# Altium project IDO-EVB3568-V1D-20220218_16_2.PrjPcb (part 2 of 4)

## Sheet P07.SchDoc
size 420 x 297 mm
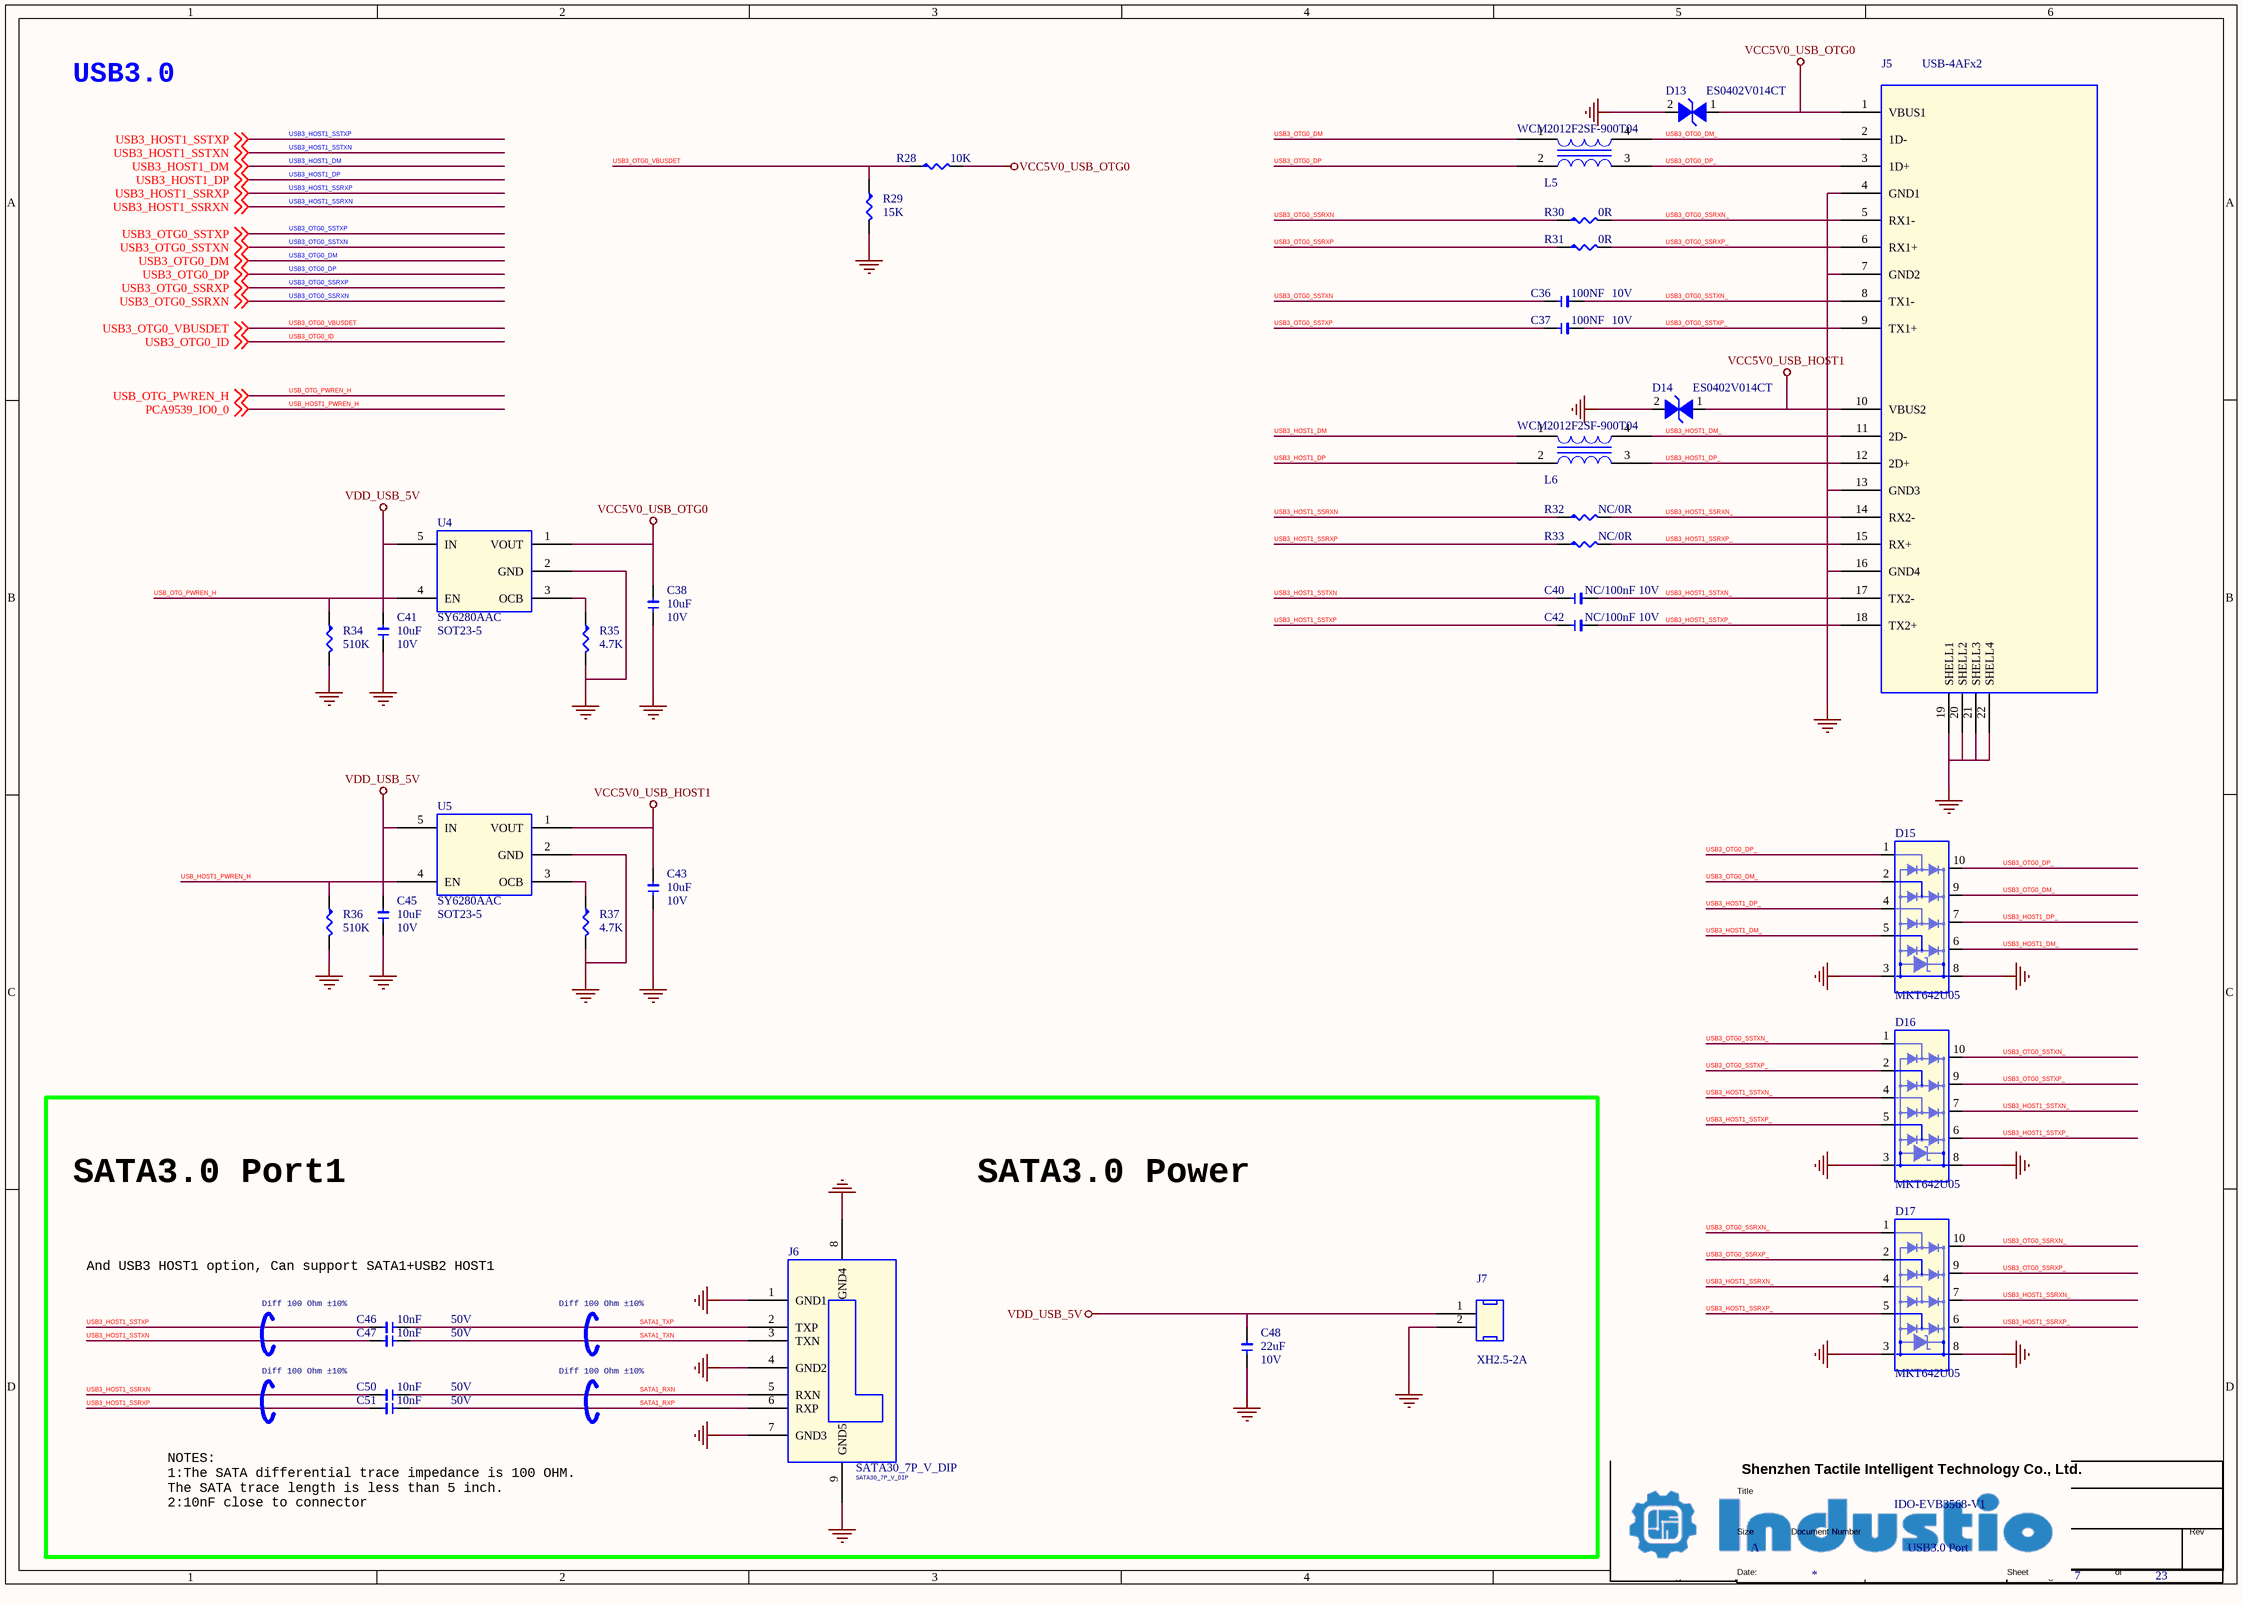
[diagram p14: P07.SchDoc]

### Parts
(Parts that share a designator on the sheet are numbered #1, #2 ... from top to bottom, then left to right.)
*#7  Doc: USB3.0 Port  Title: IDO-EVB3568-V1  Page Size: A  Page Number: 7  Page Count: 23  (hidden comment: TitleBlock1)  (graphical)
C36  100NF  DSC2: 10V  [1206]
C37  100NF  DSC2: 10V  [1206]
C38  10uF  DSC2: 10V  [1206]
C40  NC/100nF  DSC2: 10V  [1206]
C41  10uF  DSC2: 10V  [1206]
C42  NC/100nF  DSC2: 10V  [1206]
C43  10uF  DSC2: 10V  [1206]
C45  10uF  DSC2: 10V  [1206]
C46  10nF  DSC2: 50V  [1206]
C47  10nF  DSC2: 50V  [1206]
C48  22uF  DSC2: 10V  [1206]
C50  10nF  DSC2: 50V  [1206]
C51  10nF  DSC2: 50V  [1206]
D13  ES0402V014CT  [V0402]
D14  ES0402V014CT  [V0402]
D15  MKT642U05  [ESD-DFN2510A-10]
D16  MKT642U05  [ESD-DFN2510A-10]
D17  MKT642U05  [ESD-DFN2510A-10]
J5  USB-4AFx2  [USB3D0_AF_18P]
J6  SATA30_7P_V_DIP  [SATA30_7P_V_DIP]
J7  XH2.5-2A  [XH250-2A]
L5  WCM2012F2SF-900T04  [CMLS-ACM2012]
L6  WCM2012F2SF-900T04  [CMLS-ACM2012]
R28  10K  [R0402L]
R29  15K  [R0402L]
R30  0R  [R0402L]
R31  0R  [R0402L]
R32  NC/0R  [R0402L]
R33  NC/0R  [R0402L]
R34  510K  [R0402L]
R35  4.7K  [R0402L]
R36  510K  [R0402L]
R37  4.7K  [R0402L]
U4  SY6280AAC  [SOT23-5]
U5  SY6280AAC  [SOT23-5]

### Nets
GND: C38.1 C41.1 C43.1 C45.1 C48.1 D13.2(I/O1) D14.2(I/O1) D15.3 D15.8 D16.3 D16.8 D17.3 D17.8 J5.4(GND1) J5.7(GND2) J5.13(GND3) J5.16(GND4) J5.19(SHELL1) J5.20(SHELL2) J5.21(SHELL3) J5.22(SHELL4) J6.1(GND1) J6.4(GND2) J6.7(GND3) J6.8(GND4) J6.9(GND5) J7.2 R29.2 R34.2 R35.2 R36.2 R37.2 U4.2(GND) U5.2(GND)
VCC5V0_USB_HOST1: C43.2 D14.1(I/O2) J5.10(VBUS2) U5.1(VOUT)
VCC5V0_USB_OTG0: C38.2 D13.1(I/O2) J5.1(VBUS1) R28.2 U4.1(VOUT)
VDD_USB_5V: C41.2 C45.2 C48.2 J7.1 U4.5(IN) U5.5(IN)
PCA9539_IO0_0: R36.1 U5.4(EN) ; off-sheet PCA9539_IO0_0  [also labelled USB_HOST1_PWREN_H]
SATA1_RXN: C50.1 J6.5(RXN)
SATA1_RXP: C51.1 J6.6(RXP)
SATA1_TXN: C47.1 J6.3(TXN)
SATA1_TXP: C46.1 J6.2(TXP)
USB3_HOST1_DM: L6.1 ; off-sheet USB3_HOST1_DM
USB3_HOST1_DM_: D15.5 D15.6 J5.11(2D-) L6.4
USB3_HOST1_DP: L6.2 ; off-sheet USB3_HOST1_DP
USB3_HOST1_DP_: D15.4 D15.7 J5.12(2D+) L6.3
USB3_HOST1_SSRXN: C50.2 R32.1 ; off-sheet USB3_HOST1_SSRXN
USB3_HOST1_SSRXN_: D17.4 D17.7 J5.14(RX2-) R32.2
USB3_HOST1_SSRXP: C51.2 R33.1 ; off-sheet USB3_HOST1_SSRXP
USB3_HOST1_SSRXP_: D17.5 D17.6 J5.15(RX+) R33.2
USB3_HOST1_SSTXN: C40.1 C47.2 ; off-sheet USB3_HOST1_SSTXN
USB3_HOST1_SSTXN_: C40.2 D16.4 D16.7 J5.17(TX2-)
USB3_HOST1_SSTXP: C42.1 C46.2 ; off-sheet USB3_HOST1_SSTXP
USB3_HOST1_SSTXP_: C42.2 D16.5 D16.6 J5.18(TX2+)
USB3_OTG0_DM: L5.1 ; off-sheet USB3_OTG0_DM
USB3_OTG0_DM_: D15.2 D15.9 J5.2(1D-) L5.4
USB3_OTG0_DP: L5.2 ; off-sheet USB3_OTG0_DP
USB3_OTG0_DP_: D15.1 D15.10 J5.3(1D+) L5.3
USB3_OTG0_SSRXN: R30.1 ; off-sheet USB3_OTG0_SSRXN
USB3_OTG0_SSRXN_: D17.1 D17.10 J5.5(RX1-) R30.2
USB3_OTG0_SSRXP: R31.1 ; off-sheet USB3_OTG0_SSRXP
USB3_OTG0_SSRXP_: D17.2 D17.9 J5.6(RX1+) R31.2
USB3_OTG0_SSTXN: C36.1 ; off-sheet USB3_OTG0_SSTXN
USB3_OTG0_SSTXN_: C36.2 D16.1 D16.10 J5.8(TX1-)
USB3_OTG0_SSTXP: C37.1 ; off-sheet USB3_OTG0_SSTXP
USB3_OTG0_SSTXP_: C37.2 D16.2 D16.9 J5.9(TX1+)
USB3_OTG0_VBUSDET: R28.1 R29.1 ; off-sheet USB3_OTG0_VBUSDET
USB_OTG_PWREN_H: R34.1 U4.4(EN) ; off-sheet USB_OTG_PWREN_H  [project net SDMMC0_PWREN/SATA_MP_SWITCH/PCIE20_CLKREQn_M0/GPIO0_A5_d]
NetR35_1: R35.1 U4.3(OCB)
NetR37_1: R37.1 U5.3(OCB)

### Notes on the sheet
- USB3.0
- SATA3.0 Port1
- SATA3.0 Power
- And USB3 HOST1 option, Can support SATA1+USB2 HOST1
- Diff 100 Ohm ±10%
- NOTES:
  1:The SATA differential trace impedance is 100 OHM.
  The SATA trace length is less than 5 inch.
  2:10nF close to connector

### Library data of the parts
C36 C40 = C-0402_Dup1: Part Number: C020102120060; Part Name: 贴片电容; Manufacture: 三星¦国巨¦村田; PCB Footprint: C0402L; DSC1: ±10%; DSC3: X7R; ID: 60
C37 C42 = C-0402_Dup1: Manufacture: 三星¦国巨¦村田; Part Name: 贴片电容; Part Number: C020102120060; PCB Footprint: C0402L; ID: 60; DSC3: X7R; DSC1: ±10%
C38 = C-0603: Manufacture: 三星¦国巨¦村田; Part Name: 贴片电容; Part Number: C020102120071; ID: 71; DSC3: X5R; DSC1: ±20%; ERP Number: 1010200076; PCB Footprint: C0603L
C41 = C-0603: Part Number: C020102120071; Part Name: 贴片电容; Manufacture: 三星¦国巨¦村田; PCB Footprint: C0603L; ERP Number: 1010200076; DSC1: ±20%; DSC3: X5R; ID: 71
C43 = C-0603: Part Number: C020102120071; Part Name: 贴片电容; Manufacture: 三星¦国巨¦村田; ERP Number: 1010200076; DSC1: ±20%; DSC3: X5R; ID: 71; PCB Footprint: C0603L
C45 = C-0603: Manufacture: 三星¦国巨¦村田; Part Name: 贴片电容; Part Number: C020102120071; PCB Footprint: C0603L; ID: 71; DSC3: X5R; DSC1: ±20%; ERP Number: 1010200076
C46 C47 C50 C51 = C-0402_Dup1: Part Number: C020102120057; Part Name: 贴片电容; Manufacture: 三星¦国巨¦村田; PCB Footprint: C0402L; ERP Number: 1010200077; DSC1: ±10%; DSC3: X7R; ID: 57
C48 = C-0805: Manufacture: 三星¦国巨¦村田; Part Name: 贴片电容; Part Number: C020102120075; PCB Footprint: C0805L; ID: 75; DSC3: X5R; DSC1: ±20%
D13 = DI-ESD: ESD 0402; Part Number: C040502250002; Manufacture P/N: MLVG04021R0UV18; Manufacturer: INPAQ; Manufacture: AEM; PN Type: Varistor; ERP Number: 1010800023; DSC1: 双向; DSC2: Vdc=14V; DSC3: Vbr=300V; DSC4: Vc=30V; DSC5: Cj=0.25pF; ID: 2
D14 = DI-ESD: ESD 0402; Part Number: C040502250002; Manufacture P/N: MLVG04021R0UV18; Manufacturer: INPAQ; Manufacture: AEM; PN Type: Varistor; ID: 2; DSC5: Cj=0.25pF; DSC4: Vc=30V; DSC3: Vbr=300V; DSC2: Vdc=14V; DSC1: 双向; ERP Number: 1010800023
D15-D17 = DI-ESD-MKT642U05: Manufacture: 米客方德; Part Number: C040502250008; Part Name: ESD; Solder: 推荐; ID: 8; DSC5: Cj=0.35pF; DSC4: Vc=16V; DSC3: Vbr=6V; DSC2: Vdc=5V
J5 = J-USB-4AFX2-DIP_1: USB,TYPE-A,2PORT,R/A,W/SHIELD; Part Name: USB连接器; VSTNO: H00025; DSC1: USB AF_18P 双层 DIP 90° 铁壳 弯脚  白色; DSC2: 17.6*14.5*15.7mm; DSC3: 通孔弯针; ID: 6
J6 = SATA_DIP_0
J7 = J-H-2P: Part Name: XH; Part Number: J020602850001; ID: 31; DSC5: XH-2AK米(博穆精密); DSC4: 米黄色胶壳 耐高温; DSC3: 通孔180度直针; DSC2: 2.5mm间距; DSC1: 2p
L5 = L-CMLS-ACM2012: Part Name: 信号共模电感; Part Number: C060402360001; Manufacture: 台庆; ERP Number: 1010200196; DSC1: 90uH@100kHz; DSC2: 90Ω@100MHz; DSC3: 400mA; DSC4: DCR=300mΩ; DSC5: -40℃ ~ +125℃; DSC6: SMD_4P,2x1.2mm; ID: 1
L6 = L-CMLS-ACM2012: Manufacture: 台庆; Part Number: C060402360001; Part Name: 信号共模电感; ID: 1; DSC6: SMD_4P,2x1.2mm; DSC5: -40℃ ~ +125℃; DSC4: DCR=300mΩ; DSC3: 400mA; DSC2: 90Ω@100MHz; DSC1: 90uH@100kHz; ERP Number: 1010200196
R28 = R-0402_Dup1: Part Name: 贴片电阻; Part Number: C011002080856; ERP Number: 1010200140; DSC1: ±1%; DSC2: 1/16W; ID: 856
R29 = R-0402_Dup1: Part Name: 贴片电阻; Part Number: C011002080875; ERP Number: 1010200458; DSC1: ±1%; DSC2: 1/16W; ID: 875
R30 R33 = R-0402_Dup1: Part Name: 贴片电阻; Part Number: C011002080413; DSC1: ±1%; DSC2: 1/16W; ID: 413
R31 R32 = R-0402_Dup1: Part Number: C011002080413; Part Name: 贴片电阻; ID: 413; DSC2: 1/16W; DSC1: ±1%
R34 = R-0402_Dup1: Part Number: C011002081059; Part Name: 贴片电阻; ID: 1,059; DSC2: 1/16W; DSC1: ±1%; ERP Number: 1010200459
R35 = R-0402_Dup1: Part Name: 贴片电阻; Part Number: C011002080818; ERP Number: 1010200445; DSC1: ±1%; DSC2: 1/16W; ID: 818
R36 = R-0402_Dup1: Part Name: 贴片电阻; Part Number: C011002081059; ERP Number: 1010200459; DSC1: ±1%; DSC2: 1/16W; ID: 1,059
R37 = R-0402_Dup1: Part Number: C011002080818; Part Name: 贴片电阻; ID: 818; DSC2: 1/16W; DSC1: ±1%; ERP Number: 1010200445
U4 = U-SY6280AAC: Manufacture: 矽力杰; Part Name: 功率开关; Part Number: C070402430001; ID: 1; DSC4: -40~85℃; DSC3: 80m?; DSC2: 2.4-5.5V 2A; DSC1: 低能耗电源开关; ERP Number: 1010100222
U5 = U-SY6280AAC: Part Number: C070402430001; Part Name: 功率开关; Manufacture: 矽力杰; ERP Number: 1010100222; DSC1: 低能耗电源开关; DSC2: 2.4-5.5V 2A; DSC3: 80m?; DSC4: -40~85℃; ID: 1

## Sheet P08.SchDoc
size 594 x 420 mm
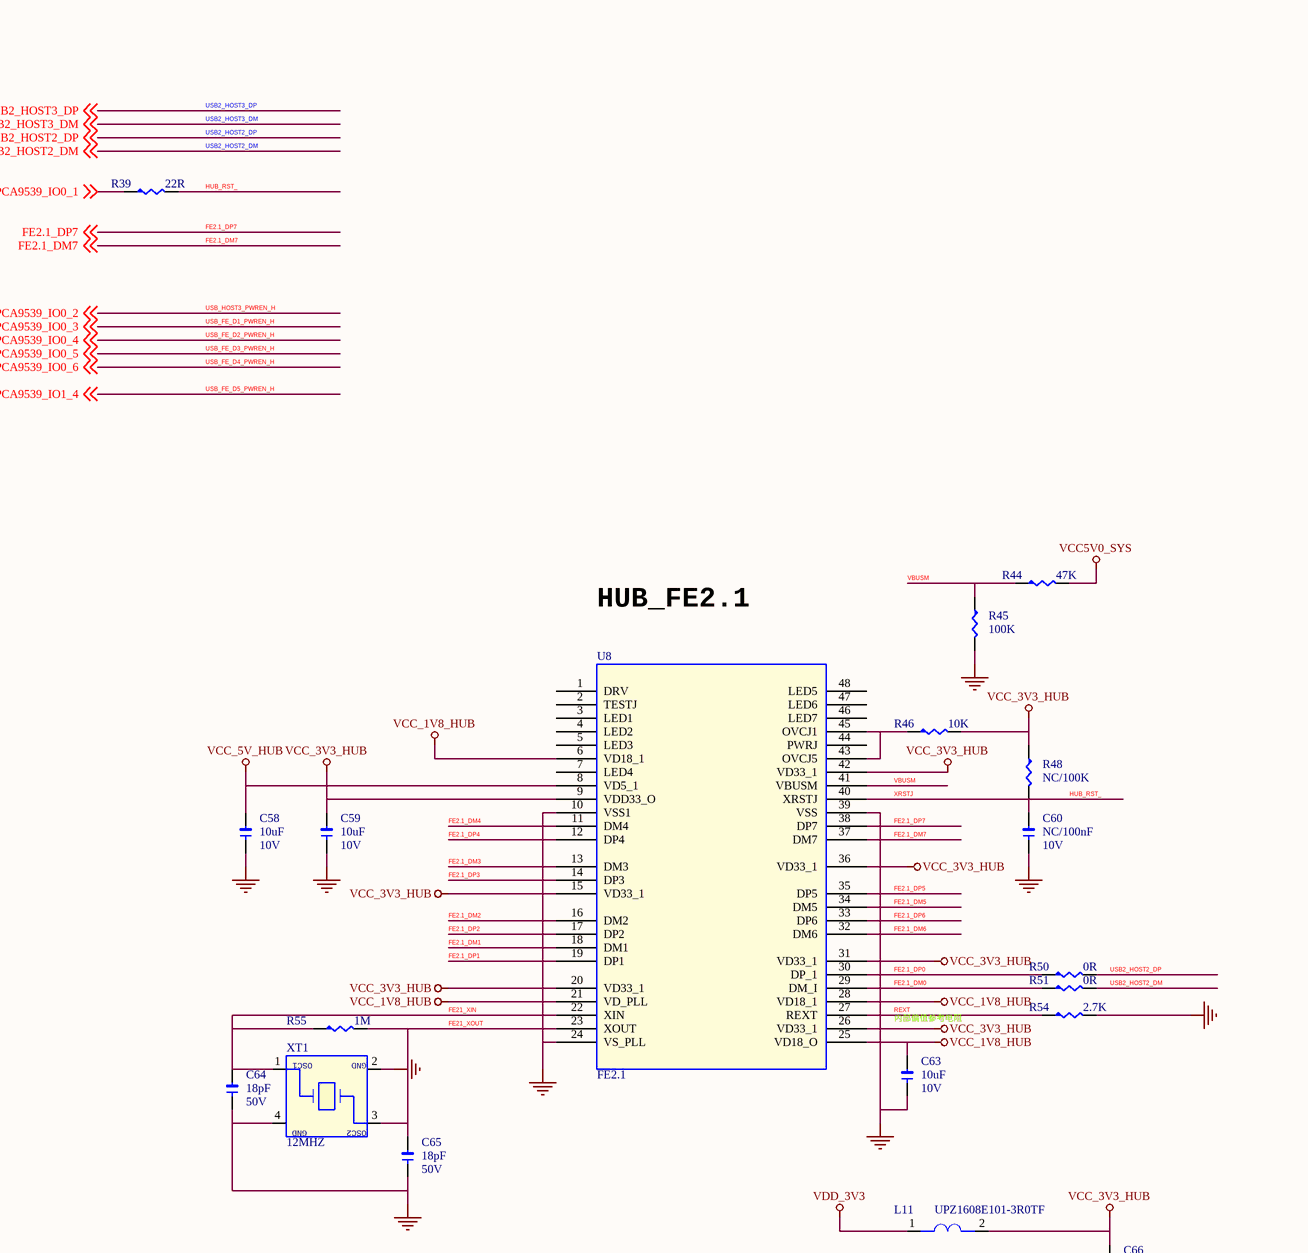
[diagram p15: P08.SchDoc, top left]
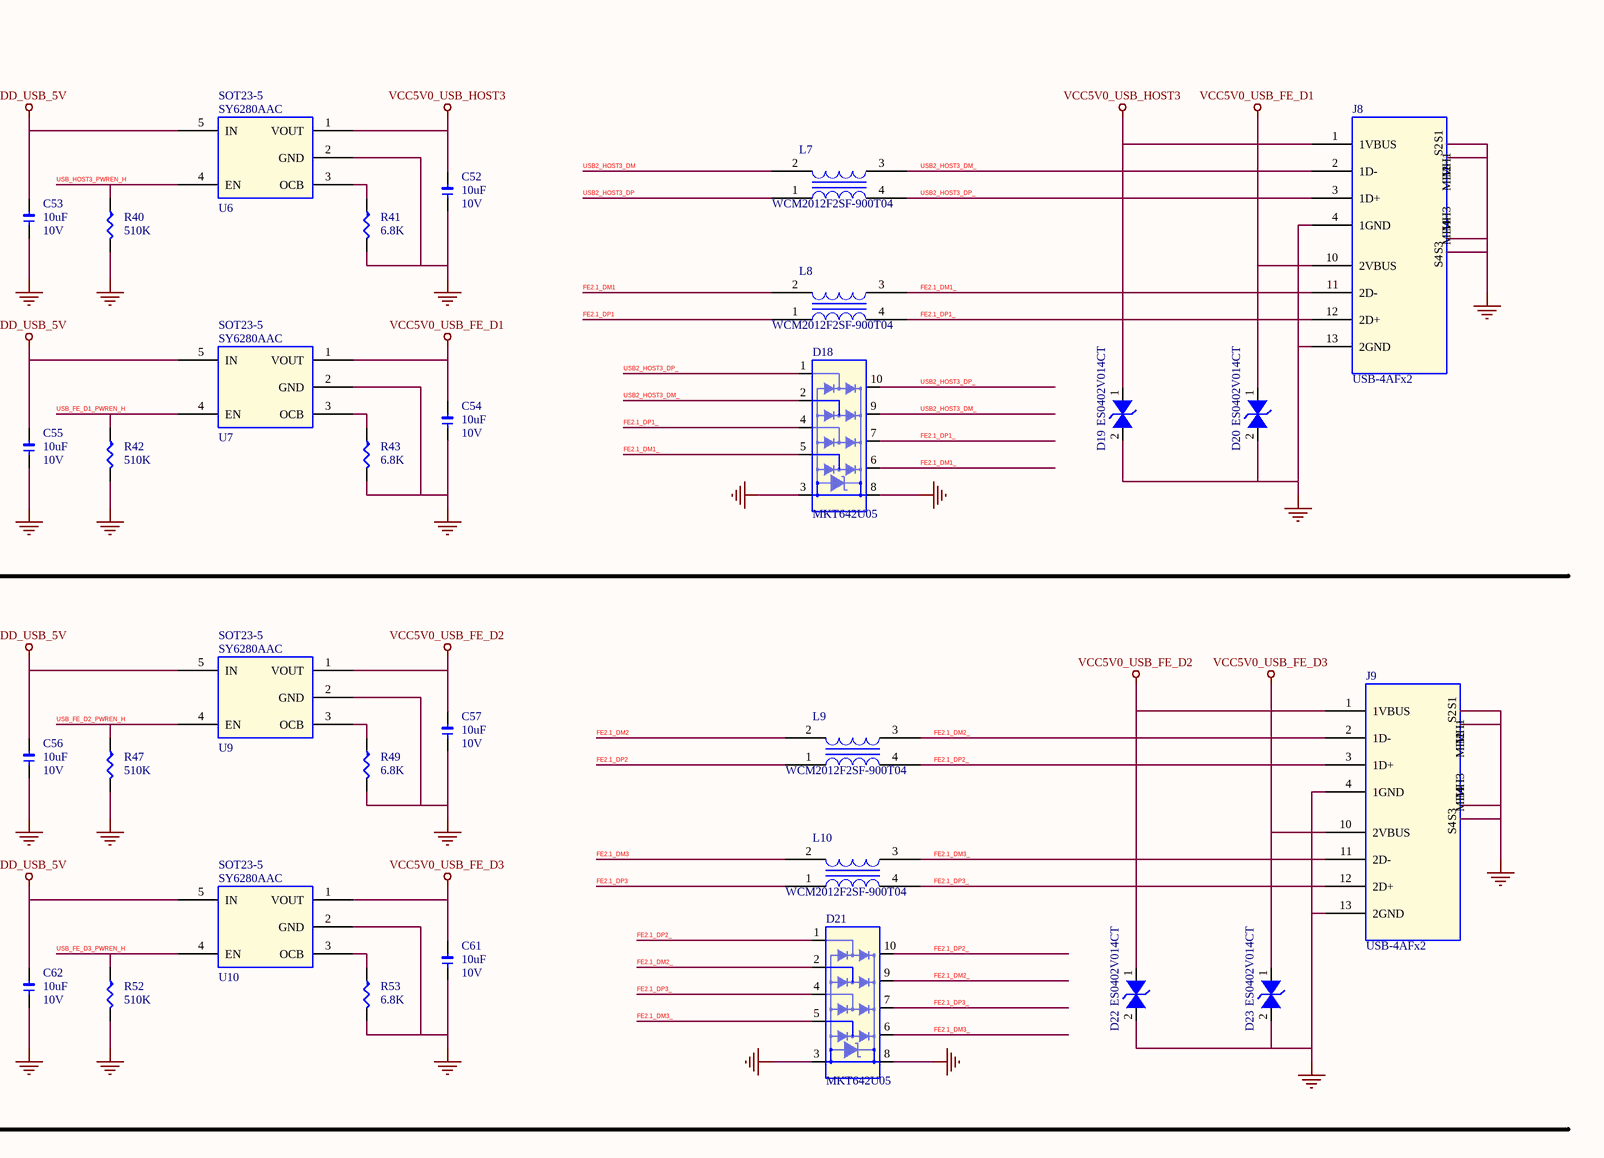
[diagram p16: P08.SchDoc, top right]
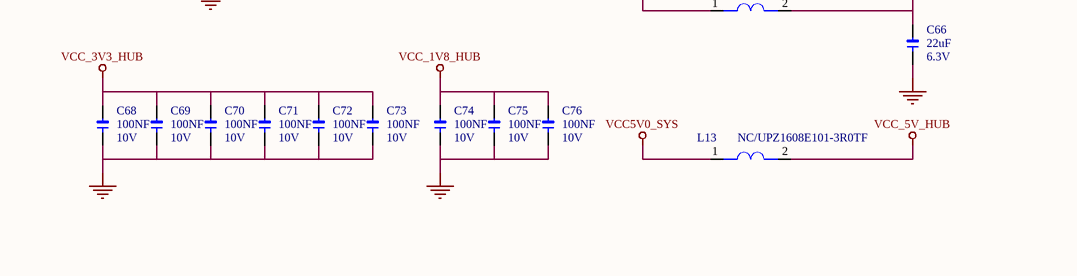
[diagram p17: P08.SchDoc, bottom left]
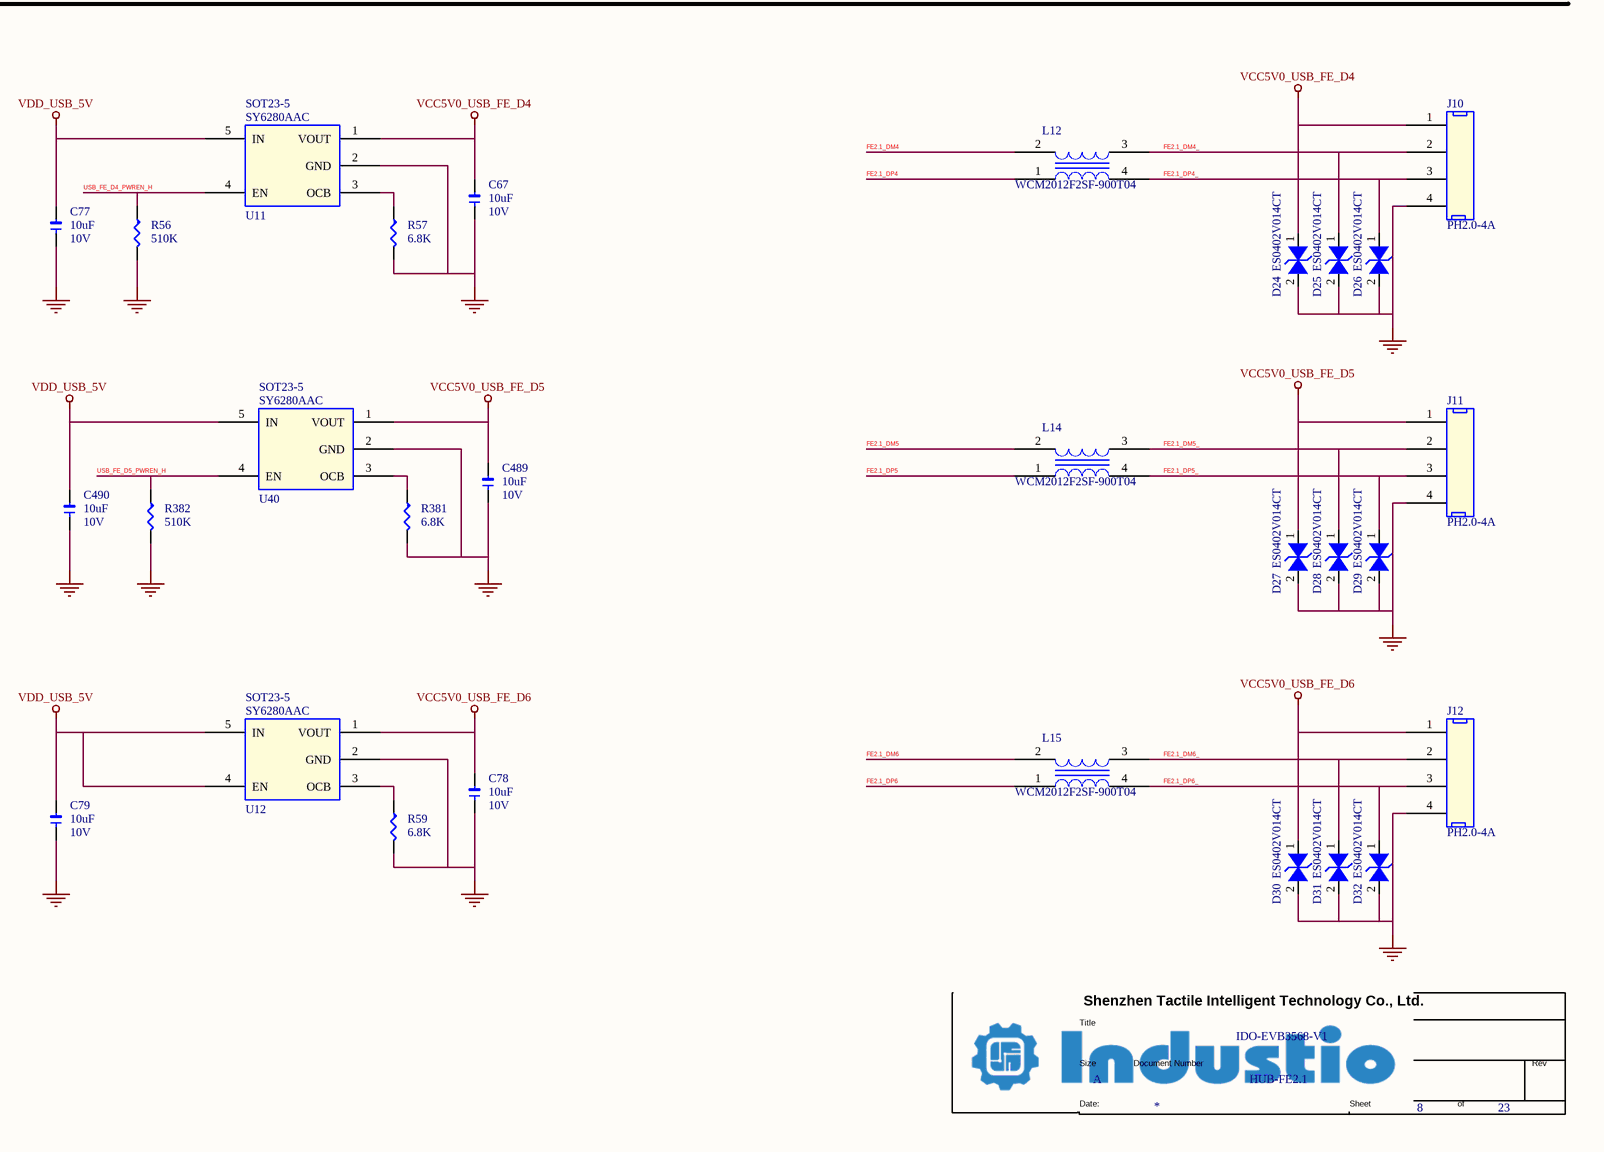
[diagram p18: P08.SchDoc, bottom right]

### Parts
(Parts that share a designator on the sheet are numbered #1, #2 ... from top to bottom, then left to right.)
*#8  Doc: HUB-FE2.1  Title: IDO-EVB3568-V1  Page Size: A  Page Number: 8  Page Count: 23  (hidden comment: TitleBlock1)  (graphical)
C52  10uF  DSC2: 10V  [1206]
C53  10uF  DSC2: 10V  [1206]
C54  10uF  DSC2: 10V  [1206]
C55  10uF  DSC2: 10V  [1206]
C56  10uF  DSC2: 10V  [1206]
C57  10uF  DSC2: 10V  [1206]
C58  10uF  DSC2: 10V  [1206]
C59  10uF  DSC2: 10V  [1206]
C60  NC/100nF  DSC2: 10V  [1206]
C61  10uF  DSC2: 10V  [1206]
C62  10uF  DSC2: 10V  [1206]
C63  10uF  DSC2: 10V  [1206]
C64  18pF  DSC2: 50V  [1206]
C65  18pF  DSC2: 50V  [1206]
C66  22uF  DSC2: 6.3V  [1206]
C67  10uF  DSC2: 10V  [1206]
C68  100NF  DSC2: 10V  [1206]
C69  100NF  DSC2: 10V  [1206]
C70  100NF  DSC2: 10V  [1206]
C71  100NF  DSC2: 10V  [1206]
C72  100NF  DSC2: 10V  [1206]
C73  100NF  DSC2: 10V  [1206]
C74  100NF  DSC2: 10V  [1206]
C75  100NF  DSC2: 10V  [1206]
C76  100NF  DSC2: 10V  [1206]
C77  10uF  DSC2: 10V  [1206]
C78  10uF  DSC2: 10V  [1206]
C79  10uF  DSC2: 10V  [1206]
C489  10uF  DSC2: 10V  [1206]
C490  10uF  DSC2: 10V  [1206]
D18  MKT642U05  [ESD-DFN2510A-10]
D19  ES0402V014CT  [V0402]
D20  ES0402V014CT  [V0402]
D21  MKT642U05  [ESD-DFN2510A-10]
D22  ES0402V014CT  [V0402]
D23  ES0402V014CT  [V0402]
D24  ES0402V014CT  [V0402]
D25  ES0402V014CT  [V0402]
D26  ES0402V014CT  [V0402]
D27  ES0402V014CT  [V0402]
D28  ES0402V014CT  [V0402]
D29  ES0402V014CT  [V0402]
D30  ES0402V014CT  [V0402]
D31  ES0402V014CT  [V0402]
D32  ES0402V014CT  [V0402]
J8  USB-4AFx2  [dural_usb_af_2x]
J9  USB-4AFx2  [dural_usb_af_2x]
J10  PH2.0-4A  [PH200-4A]
J11  PH2.0-4A  [PH200-4A]
J12  PH2.0-4A  [PH200-4A]
L7  WCM2012F2SF-900T04  [CMLS-ACM2012]
L8  WCM2012F2SF-900T04  [CMLS-ACM2012]
L9  WCM2012F2SF-900T04  [CMLS-ACM2012]
L10  WCM2012F2SF-900T04  [CMLS-ACM2012]
L11  UPZ1608E101-3R0TF  [L0603]
L12  WCM2012F2SF-900T04  [CMLS-ACM2012]
L13  NC/UPZ1608E101-3R0TF  [L0603]
L14  WCM2012F2SF-900T04  [CMLS-ACM2012]
L15  WCM2012F2SF-900T04  [CMLS-ACM2012]
R39  22R  [R0402L]
R40  510K  [R0402L]
R41  6.8K  [R0402L]
R42  510K  [R0402L]
R43  6.8K  [R0402L]
R44  47K  [R0402L]
R45  100K  [R0402L]
R46  10K  [R0402L]
R47  510K  [R0402L]
R48  NC/100K  [R0402L]
R49  6.8K  [R0402L]
R50  0R  [R0402L]
R51  0R  [R0402L]
R52  510K  [R0402L]
R53  6.8K  [R0402L]
R54  2.7K  [R0402L]
R55  1M  [R0402L]
R56  510K  [R0402L]
R57  6.8K  [R0402L]
R59  6.8K  [R0402L]
R381  6.8K  [R0402L]
R382  510K  [R0402L]
U6  SY6280AAC  [SOT23-5]
U7  SY6280AAC  [SOT23-5]
U8  FE2.1  [FE2_1-LQFP48]
U9  SY6280AAC  [SOT23-5]
U10  SY6280AAC  [SOT23-5]
U11  SY6280AAC  [SOT23-5]
U12  SY6280AAC  [SOT23-5]
U40  SY6280AAC  [SOT23-5]
XT1  12MHZ  [xtal_32x25_4p]

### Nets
GND: C52.1 C53.1 C54.1 C55.1 C56.1 C57.1 C58.1 C59.1 C60.1 C61.1 C62.1 C63.1 C64.1 C65.1 C66.1 C67.1 C68.1 C69.1 C70.1 C71.1 C72.1 C73.1 C74.1 C75.1 C76.1 C77.1 C78.1 C79.1 C489.1 C490.1 D18.3 D18.8 D19.2(I/O1) D20.2(I/O1) D21.3 D21.8 D22.2(I/O1) D23.2(I/O1) D24.2(I/O1) D25.2(I/O1) D26.2(I/O1) D27.2(I/O1) D28.2(I/O1) D29.2(I/O1) D30.2(I/O1) D31.2(I/O1) D32.2(I/O1) J8.4(1GND) J8.13(2GND) J8.S1(MH1) J8.S2(MH2) J8.S3(MH3) J8.S4(MH4) J9.4(1GND) J9.13(2GND) J9.S1(MH1) J9.S2(MH2) J9.S3(MH3) J9.S4(MH4) J10.4 J11.4 J12.4 R40.2 R41.2 R42.2 R43.2 R45.2 R47.2 R49.2 R52.2 R53.2 R54.2 R56.2 R57.2 R59.2 R381.2 R382.2 U6.2(GND) U7.2(GND) U8.10(VSS1) U8.24(VS_PLL) U8.39(VSS) U9.2(GND) U10.2(GND) U11.2(GND) U12.2(GND) U40.2(GND) XT1.2 XT1.4
VCC5V0_SYS: L13.1 R44.2
VCC5V0_USB_FE_D1: C54.2 D20.1(I/O2) J8.10(2VBUS) U7.1(VOUT)
VCC5V0_USB_FE_D2: C57.2 D22.1(I/O2) J9.1(1VBUS) U9.1(VOUT)
VCC5V0_USB_FE_D3: C61.2 D23.1(I/O2) J9.10(2VBUS) U10.1(VOUT)
VCC5V0_USB_FE_D4: C67.2 D24.1(I/O2) J10.1 U11.1(VOUT)
VCC5V0_USB_FE_D5: C489.2 D27.1(I/O2) J11.1 U40.1(VOUT)
VCC5V0_USB_FE_D6: C78.2 D30.1(I/O2) J12.1 U12.1(VOUT)
VCC5V0_USB_HOST3: C52.2 D19.1(I/O2) J8.1(1VBUS) U6.1(VOUT)
VCC_1V8_HUB: C63.2 C74.2 C75.2 C76.2 U8.6(VD18_1) U8.21(VD_PLL) U8.25(VD18_O) U8.28(VD18_1)
VCC_3V3_HUB: C59.2 C66.2 C68.2 C69.2 C70.2 C71.2 C72.2 C73.2 L11.2 R46.2 R48.1 U8.9(VDD33_O) U8.15(VD33_1) U8.20(VD33_1) U8.26(VD33_1) U8.31(VD33_1) U8.36(VD33_1) U8.42(VD33_1)
VCC_5V_HUB: C58.2 L13.2 U8.8(VD5_1)
VDD_3V3: L11.1
VDD_USB_5V: C53.2 C55.2 C56.2 C62.2 C77.2 C79.2 C490.2 U6.5(IN) U7.5(IN) U9.5(IN) U10.5(IN) U11.5(IN) U12.4(EN) U12.5(IN) U40.5(IN)
FE2.1_DM0: R51.1 U8.29(DM_I)
FE2.1_DM1: L8.2 U8.18(DM1)
FE2.1_DM1_: D18.5 D18.6 J8.11(2D-) L8.3
FE2.1_DM2: L9.2 U8.16(DM2)
FE2.1_DM2_: D21.2 D21.9 J9.2(1D-) L9.3
FE2.1_DM3: L10.2 U8.13(DM3)
FE2.1_DM3_: D21.5 D21.6 J9.11(2D-) L10.3
FE2.1_DM4: L12.2 U8.11(DM4)
FE2.1_DM4_: D25.1(I/O2) J10.2 L12.3
FE2.1_DM5: L14.2 U8.34(DM5)
FE2.1_DM5_: D28.1(I/O2) J11.2 L14.3
FE2.1_DM6: L15.2 U8.32(DM6)
FE2.1_DM6_: D31.1(I/O2) J12.2 L15.3
FE2.1_DM7: U8.37(DM7) ; off-sheet FE2.1_DM7
FE2.1_DP0: R50.1 U8.30(DP_1)
FE2.1_DP1: L8.1 U8.19(DP1)
FE2.1_DP1_: D18.4 D18.7 J8.12(2D+) L8.4
FE2.1_DP2: L9.1 U8.17(DP2)
FE2.1_DP2_: D21.1 D21.10 J9.3(1D+) L9.4
FE2.1_DP3: L10.1 U8.14(DP3)
FE2.1_DP3_: D21.4 D21.7 J9.12(2D+) L10.4
FE2.1_DP4: L12.1 U8.12(DP4)
FE2.1_DP4_: D26.1(I/O2) J10.3 L12.4
FE2.1_DP5: L14.1 U8.35(DP5)
FE2.1_DP5_: D29.1(I/O2) J11.3 L14.4
FE2.1_DP6: L15.1 U8.33(DP6)
FE2.1_DP6_: D32.1(I/O2) J12.3 L15.4
FE2.1_DP7: U8.38(DP7) ; off-sheet FE2.1_DP7
FE21_XIN: C64.2 R55.1 U8.22(XIN) XT1.1
FE21_XOUT: C65.2 R55.2 U8.23(XOUT) XT1.3
HUB_RST_: C60.2 R39.2 R48.2 U8.40(XRSTJ)  [also labelled XRSTJ]
PCA9539_IO0_1: R39.1 ; off-sheet PCA9539_IO0_1
PCA9539_IO0_2: R40.1 U6.4(EN) ; off-sheet PCA9539_IO0_2  [also labelled USB_HOST3_PWREN_H]
PCA9539_IO0_3: R42.1 U7.4(EN) ; off-sheet PCA9539_IO0_3  [also labelled USB_FE_D1_PWREN_H]
PCA9539_IO0_4: R47.1 U9.4(EN) ; off-sheet PCA9539_IO0_4  [also labelled USB_FE_D2_PWREN_H]
PCA9539_IO0_5: R52.1 U10.4(EN) ; off-sheet PCA9539_IO0_5  [also labelled USB_FE_D3_PWREN_H]
PCA9539_IO0_6: R56.1 U11.4(EN) ; off-sheet PCA9539_IO0_6  [also labelled USB_FE_D4_PWREN_H]
PCA9539_IO1_4: R382.1 U40.4(EN) ; off-sheet PCA9539_IO1_4  [also labelled USB_FE_D5_PWREN_H]
REXT: R54.1 U8.27(REXT)
USB2_HOST2_DM: R51.2 ; off-sheet USB2_HOST2_DM
USB2_HOST2_DP: R50.2 ; off-sheet USB2_HOST2_DP
USB2_HOST3_DM: L7.2 ; off-sheet USB2_HOST3_DM
USB2_HOST3_DM_: D18.2 D18.9 J8.2(1D-) L7.3
USB2_HOST3_DP: L7.1 ; off-sheet USB2_HOST3_DP
USB2_HOST3_DP_: D18.1 D18.10 J8.3(1D+) L7.4
VBUSM: R44.1 R45.1 U8.41(VBUSM)
NetR41_1: R41.1 U6.3(OCB)
NetR43_1: R43.1 U7.3(OCB)
NetR46_1: R46.1 U8.43(OVCJ5) U8.45(OVCJ1)
NetR49_1: R49.1 U9.3(OCB)
NetR53_1: R53.1 U10.3(OCB)
NetR57_1: R57.1 U11.3(OCB)
NetR59_1: R59.1 U12.3(OCB)
NetR381_1: R381.1 U40.3(OCB)

Not connected (* = marked no-connect by the designer): U8 1(DRV) 2(TESTJ) 3(LED1) 4(LED2) 5(LED3) 7(LED4) 44(PWRJ) 46(LED7) 47(LED6) 48(LED5)

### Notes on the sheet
- HUB_FE2.1
- 内部偏值参考电阻

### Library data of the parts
C52 C54 C56 C62 C77 C78 = C-0603: as C45 on sheet P07
C53 C55 C57 C61 C67 C79 = C-0603: as C41 on sheet P07
C58 C490 = C-0603: as C43 on sheet P07
C59 C63 C489 = C-0603: as C38 on sheet P07
C60 C68-C73 = C-0402_Dup1: Manufacture: 三星¦国巨¦村田; Part Name: 贴片电容; Part Number: C020102120060; ID: 60; DSC3: X7R; DSC1: ±10%; PCB Footprint: C0402L
C64 C65 = C-0402_Dup1: Part Number: C020102120027; Part Name: 贴片电容; Manufacture: 三星¦国巨¦村田; ERP Number: 1010200091; DSC1: ±5%; DSC3: C0G; ID: 27; PCB Footprint: C0402L
C66 = C-0603: Manufacture: 三星¦国巨¦村田; Part Name: 贴片电容; Part Number: C020102120072; ID: 72; DSC3: X5R; DSC1: ±20%; ERP Number: 1010200133; PCB Footprint: C0603L
C74-C76 = C-0402_Dup1: Part Number: C020102120060; Part Name: 贴片电容; Manufacture: 三星¦国巨¦村田; DSC1: ±10%; DSC3: X7R; ID: 60; PCB Footprint: C0402L
D18 D21 = DI-ESD-MKT642U05: Part Name: ESD; Part Number: C040502250008; Manufacture: 米客方德; DSC2: Vdc=5V; DSC3: Vbr=6V; DSC4: Vc=16V; DSC5: Cj=0.35pF; ID: 8; Solder: 推荐
D19 D20 D22-D32 = DI-ESD: as D13 on sheet P07
J8 J9 = J-USB-4AFx2-DIP_2: USB,TYPE-A,2PORT,R/A,W/SHIELD; Part Number: J060102960006; Part Name: USB连接器; VSTNO: H00025; DSC1: USB AF 双层 DIP 90° 铁壳 弯脚  白色; DSC2: 17.6*14.5*15.7mm; DSC3: 通孔弯针; DSC4: C2341(LC); ID: 6
J10-J12 = J-H-4P_0: Part Number: J020302820003; Part Name: PH; DSC1: 4p; DSC2: 2.0mm间距; DSC3: 通孔180度直针; DSC4: 米黄色胶壳 耐高温; DSC5: A2001WV-4P(CJT); ID: 13
L7 L9 = L-CMLS-ACM2012: as L6 on sheet P07
L8 L10 L12 L14 L15 = L-CMLS-ACM2012: as L5 on sheet P07
L11 = FB-0603: SMD Multilayer Ferrite Chip Bead,3A,30Ohm,0.03R; Part Number: C060502370005; Manufacture P/N: PZ1608D300-3R0TF; Manufacture2 P/N: PBY160808T-400Y-N; Manufacturer: SUNLORD; Manufacture: 顺络; Part Name: 贴片磁珠; PN Type: SMD FERRITE BEAD; ID: 5; DSC4: 电源线; DSC3: DCR=30mΩ; DSC1: 100Ω@100MHz; ERP Number: 1010200207
L13 = FB-0603: SMD Multilayer Ferrite Chip Bead,3A,30Ohm,0.03R; Part Number: C060502370005; Manufacture P/N: PZ1608D300-3R0TF; Manufacture2 P/N: PBY160808T-400Y-N; Manufacturer: SUNLORD; Part Name: 贴片磁珠; Manufacture: 顺络; PN Type: SMD FERRITE BEAD; ERP Number: 1010200207; DSC1: 100Ω@100MHz; DSC3: DCR=30mΩ; DSC4: 电源线; ID: 5
R39 = R-0402_Dup1: Part Name: 贴片电阻; Part Number: C011002080552; DSC1: ±1%; DSC2: 1/16W; ID: 552
R40 R42 R382 = R-0402_Dup1: as R34 on sheet P07
R41 R43 R59 R381 = R-0402_Dup1: Part Name: 贴片电阻; Part Number: C011002080837; ERP Number: 1010200334; DSC1: ±1%; DSC2: 1/16W; ID: 837
R44 = R-0402_Dup1: Part Name: 贴片电阻; Part Number: C011002080935; ERP Number: 1010200446; DSC1: ±1%; DSC2: 1/16W; ID: 935
R45 R48 = R-0402_Dup1: Part Name: 贴片电阻; Part Number: C011002080976; ERP Number: 1010200137; DSC1: ±1%; DSC2: 1/16W; ID: 976
R46 = R-0402_Dup1: Part Number: C011002080856; Part Name: 贴片电阻; ID: 856; DSC2: 1/16W; DSC1: ±1%; ERP Number: 1010200140
R47 R52 R56 = R-0402_Dup1: as R36 on sheet P07
R49 R53 R57 = R-0402_Dup1: Part Number: C011002080837; Part Name: 贴片电阻; ID: 837; DSC2: 1/16W; DSC1: ±1%; ERP Number: 1010200334
R50 R51 = R-0402_Dup1: as R31 on sheet P07
R54 = R-0402_Dup1: Part Name: 贴片电阻; Part Number: C011002080789; DSC1: ±1%; DSC2: 1/16W; ID: 789
R55 = R-0402_Dup1: Part Number: C011002081093; Part Name: 贴片电阻; ID: 1,093; DSC2: 1/16W; DSC1: ±1%; ERP Number: 1010200470
U6 U7 U12 U40 = U-SY6280AAC: as U5 on sheet P07
U8 = U-FE2.1: Part Number: C100202500010; Part Name: USB芯片; Manufacture: TERMINUS; DSC1: USB 2.0 HIGH SPEED 7-PORT HUB CONTROLLER; DSC2: 48 PIN LQFP - 7mmX7mm,0.5 Pitch; ID: 21
U9-U11 = U-SY6280AAC: as U4 on sheet P07
XT1 = XTAL-4P: Part Name: 贴片无源晶振; Part Number: C050102290004; Manufacture: 泰晶; CLASS: IC; ERP Number: 1010700002; DSC1: 100Ω; DSC2: ±10ppm; DSC3: 12pF; DSC4: -40℃~+85℃; DSC5: 3.2*2.5mm 4P; ID: 4

## Sheet P09.SchDoc
size 297 x 209 mm
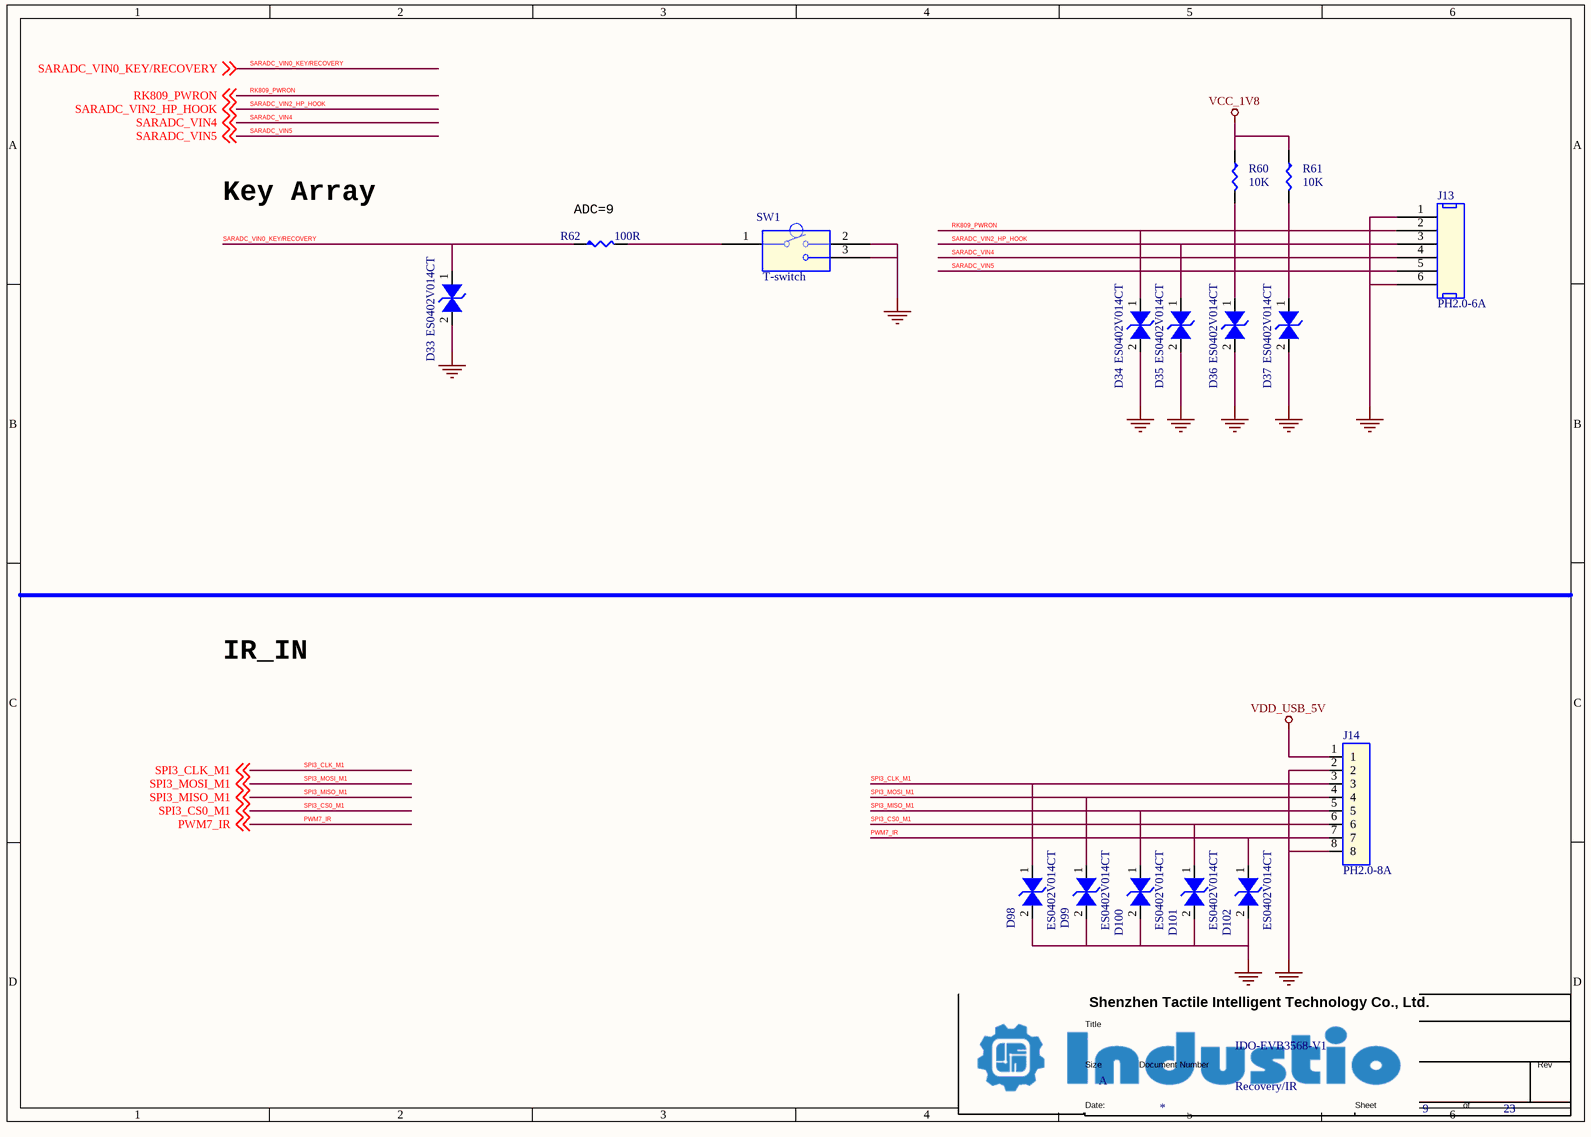
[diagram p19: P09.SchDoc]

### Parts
(Parts that share a designator on the sheet are numbered #1, #2 ... from top to bottom, then left to right.)
*#9  Doc: Recovery/IR  Title: IDO-EVB3568-V1  Page Size: A  Page Number: 9  Page Count: 23  (hidden comment: TitleBlock1)  (graphical)
D33  ES0402V014CT  [V0402]
D34  ES0402V014CT  [V0402]
D35  ES0402V014CT  [V0402]
D36  ES0402V014CT  [V0402]
D37  ES0402V014CT  [V0402]
D98  ES0402V014CT  [V0402]
D99  ES0402V014CT  [V0402]
D100  ES0402V014CT  [V0402]
D101  ES0402V014CT  [V0402]
D102  ES0402V014CT  [V0402]
J13  PH2.0-6A  [PH200-6A]
J14  PH2.0-8A  [PH200-8A]
R60  10K  [R0402L]
R61  10K  [R0402L]
R62  100R  [R0402L]
SW1  T-switch  [PB-SIDE-P-4_5x4_5]

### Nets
GND: D33.2(I/O1) D34.2(I/O1) D35.2(I/O1) D36.2(I/O1) D37.2(I/O1) D98.2(I/O1) D99.2(I/O1) D100.2(I/O1) D101.2(I/O1) D102.2(I/O1) J13.1 J13.6 J14.2 J14.8 SW1.2 SW1.3
VCC_1V8: R60.1 R61.1
VDD_USB_5V: J14.1
PWM7_IR: D102.1(I/O2) J14.7 ; off-sheet PWM7_IR
RK809_PWRON: D34.1(I/O2) J13.2 ; off-sheet RK809_PWRON
SARADC_VIN0_KEY/RECOVERY: D33.1(I/O2) R62.1 ; off-sheet SARADC_VIN0_KEY/RECOVERY
SARADC_VIN2_HP_HOOK: D35.1(I/O2) J13.3 ; off-sheet SARADC_VIN2_HP_HOOK
SARADC_VIN4: J13.4 ; off-sheet SARADC_VIN4
SARADC_VIN5: J13.5 ; off-sheet SARADC_VIN5
SPI3_CLK_M1: D98.1(I/O2) J14.3 ; off-sheet SPI3_CLK_M1  [project net PWM14_M1/SPI3_CLK_M1/CAN1_RX_M1/PCIE30X2_CLKREQn_M2/I2S3_MCLK_M1/GPIO4_C2_d]
SPI3_CS0_M1: D101.1(I/O2) J14.6 ; off-sheet SPI3_CS0_M1  [project net PWM13_M1/SPI3_CS0_M1/SATA0_ACT_LED/UART9_RX_M1/I2S3_SDI_M1/GPIO4_C6_d]
SPI3_MISO_M1: D100.1(I/O2) J14.5 ; off-sheet SPI3_MISO_M1  [project net PWM12_M1/SPI3_MISO_M1/SATA1_ACT_LED/UART9_TX_M1/I2S3_SDO_M1/GPIO4_C5_d]
SPI3_MOSI_M1: D99.1(I/O2) J14.4 ; off-sheet SPI3_MOSI_M1  [project net PWM15_IR_M1/SPI3_MOSI_M1/CAN1_TX_M1/PCIE30X2_WAKEn_M2/I2S3_SCLK_M1/GPIO4_C3_d]
NetD36_1: D36.1(I/O2) R60.2
NetD37_1: D37.1(I/O2) R61.2
NetR62_2: R62.2 SW1.1

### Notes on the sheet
- Key Array
- (near R62) ADC=9
- IR_IN

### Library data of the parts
D33 D36 D37 D102 = DI-ESD: as D14 on sheet P07
D34 D35 D98-D101 = DI-ESD: as D13 on sheet P07
J13 = J-H-6P: Part Name: PH; Part Number: J020302820005; ID: 15; DSC5: A2001WV-6P(CJT); DSC4: 米黄色胶壳 耐高温; DSC3: 通孔180度直针; DSC2: 2.0mm间距; DSC1: 6p
J14 = J-H-8P: Part Name: PH; ID: 58; DSC5: A2001WV-8P(CJT); DSC4: 米黄色胶壳 耐高温; DSC3: 通孔180度直针; DSC2: 2.0mm间距; DSC1: 8p
R60 R61 = R-0402_Dup1: as R28 on sheet P07
R62 = R-0402_Dup1: Part Name: 贴片电阻; Part Number: C011002080630; ERP Number: 1010200450; DSC1: ±1%; DSC2: 1/16W; ID: 630
SW1 = SW-K2-1109DE-C4SW-01: Part Number: C180104013837; Part Name: 轻触开关; DSC1: 轻触开关 带支架侧键 插件 柄长4.8mm; DSC2: DIP,4.5*4.5mm*4.8mm; DSC3: K2-1109DE-C4SW-01(韩荣); ID: 9

## Sheet P10.SchDoc
size 420 x 297 mm
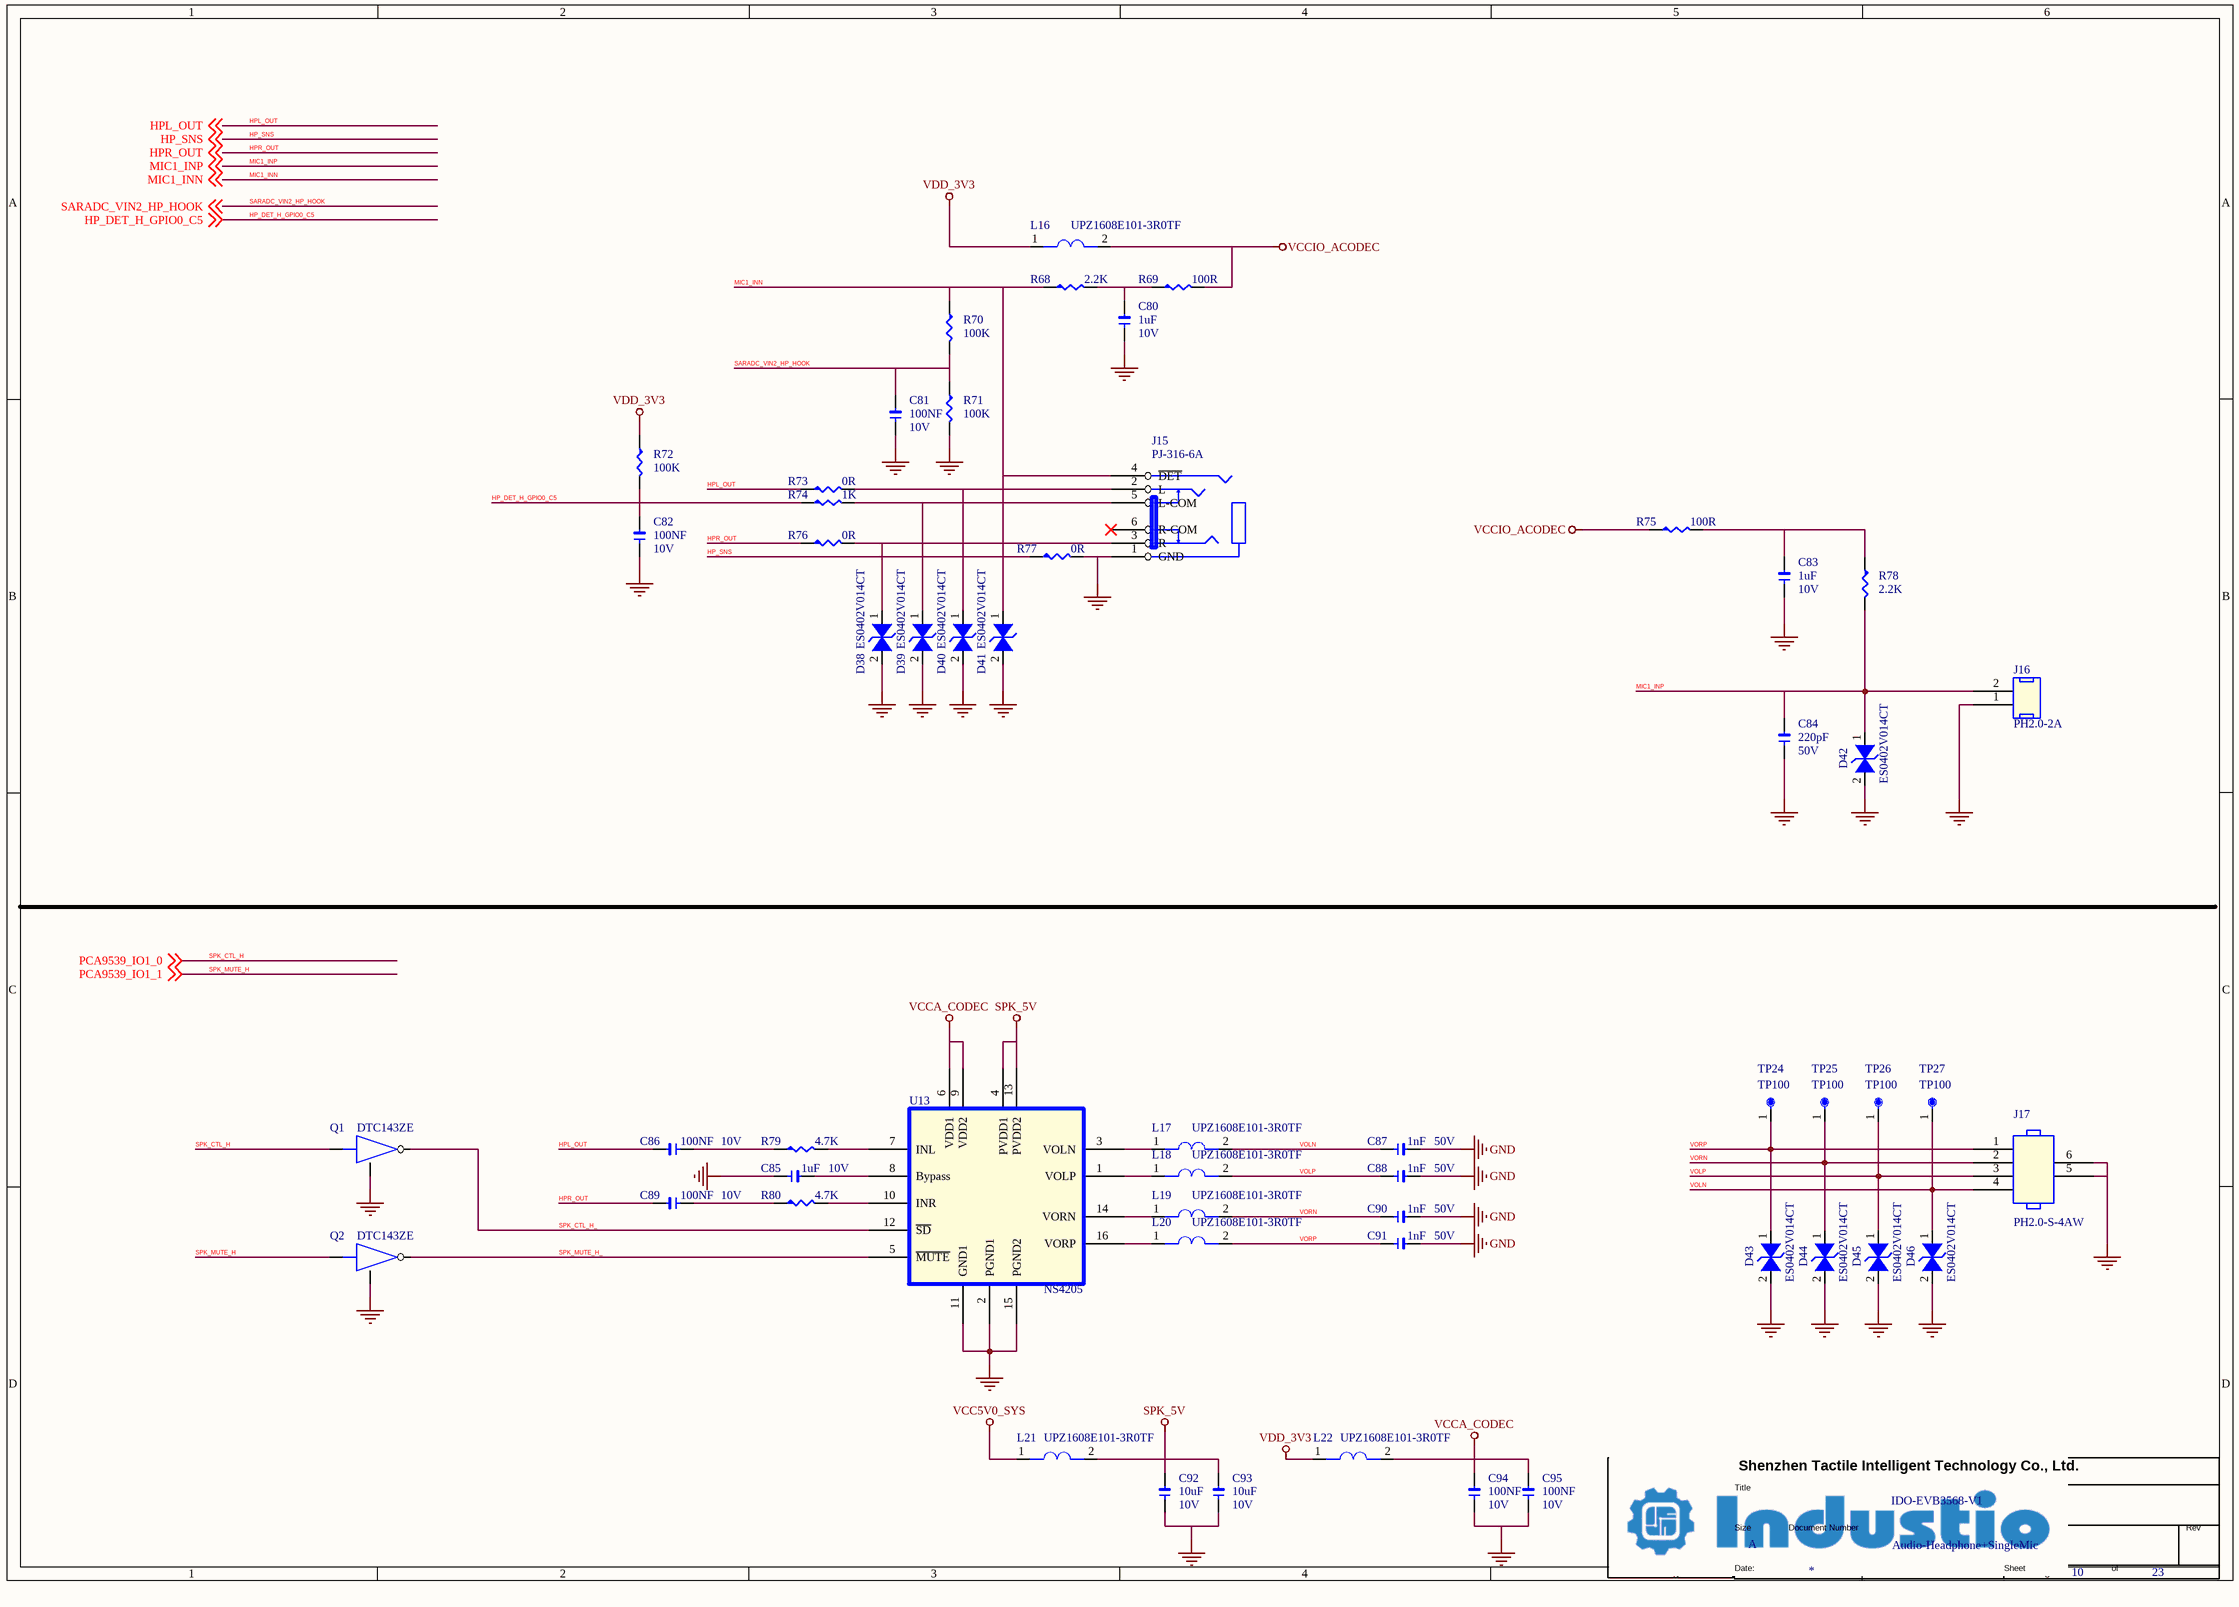
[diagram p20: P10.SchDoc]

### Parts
(Parts that share a designator on the sheet are numbered #1, #2 ... from top to bottom, then left to right.)
*#10  Doc: Audio-Headphone+SingleMic  Title: IDO-EVB3568-V1  Page Size: A  Page Number: 10  Page Count: 23  (hidden comment: TitleBlock1)  (graphical)
C80  1uF  DSC2: 10V  [1206]
C81  100NF  DSC2: 10V  [1206]
C82  100NF  DSC2: 10V  [1206]
C83  1uF  DSC2: 10V  [1206]
C84  220pF  DSC2: 50V  [1206]
C85  1uF  DSC2: 10V  [1206]
C86  100NF  DSC2: 10V  [1206]
C87  1nF  DSC2: 50V  [1206]
C88  1nF  DSC2: 50V  [1206]
C89  100NF  DSC2: 10V  [1206]
C90  1nF  DSC2: 50V  [1206]
C91  1nF  DSC2: 50V  [1206]
C92  10uF  DSC2: 10V  [1206]
C93  10uF  DSC2: 10V  [1206]
C94  100NF  DSC2: 10V  [1206]
C95  100NF  DSC2: 10V  [1206]
D38  ES0402V014CT  [V0402]
D39  ES0402V014CT  [V0402]
D40  ES0402V014CT  [V0402]
D41  ES0402V014CT  [V0402]
D42  ES0402V014CT  [V0402]
D43  ES0402V014CT  [V0402]
D44  ES0402V014CT  [V0402]
D45  ES0402V014CT  [V0402]
D46  ES0402V014CT  [V0402]
J15  PJ-316-6A  [PJ-316A-6A]
J16  PH2.0-2A  [PH200-2A]
J17  PH2.0-S-4AW  [PH200-S-4AWZ]
L16  UPZ1608E101-3R0TF  [L0603]
L17  UPZ1608E101-3R0TF  [L0603]
L18  UPZ1608E101-3R0TF  [L0603]
L19  UPZ1608E101-3R0TF  [L0603]
L20  UPZ1608E101-3R0TF  [L0603]
L21  UPZ1608E101-3R0TF  [L0603]
L22  UPZ1608E101-3R0TF  [L0603]
Q1  DTC143ZE  [SOT523]
Q2  DTC143ZE  [SOT523]
R68  2.2K  [R0402L]
R69  100R  [R0402L]
R70  100K  [R0402L]
R71  100K  [R0402L]
R72  100K  [R0402L]
R73  0R  [R0402L]
R74  1K  [R0402L]
R75  100R  [R0402L]
R76  0R  [R0402L]
R77  0R  [R0402L]
R78  2.2K  [R0402L]
R79  4.7K  [R0402L]
R80  4.7K  [R0402L]
TP24  TP100  [smd_tp_1mm]
TP25  TP100  [smd_tp_1mm]
TP26  TP100  [smd_tp_1mm]
TP27  TP100  [smd_tp_1mm]
U13  NS4205  [NS4205-SOP16]

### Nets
GND: C80.1 C81.1 C82.1 C83.1 C84.1 C85.1 C87.2 C88.2 C90.2 C91.2 C92.1 C93.1 C94.1 C95.1 D38.2(I/O1) D39.2(I/O1) D40.2(I/O1) D41.2(I/O1) D42.2(I/O1) D43.2(I/O1) D44.2(I/O1) D45.2(I/O1) D46.2(I/O1) J15.1(GND) J16.1 J17.5 J17.6 Q1.2 Q2.2 R71.2 R77.2 U13.2(PGND1) U13.11(GND1) U13.15(PGND2)
SPK_5V: C92.2 C93.2 L21.2 U13.4(PVDD1) U13.13(PVDD2)
VCC5V0_SYS: L21.1
VCCA_CODEC: C94.2 C95.2 L22.2 U13.6(VDD1) U13.9(VDD2)
VCCIO_ACODEC: L16.2 R69.2 R75.1
VDD_3V3: L16.1 L22.1 R72.1
HP_DET_H_GPIO0_C5: C82.2 R72.2 R74.1 ; off-sheet HP_DET_H_GPIO0_C5
HP_SNS: R77.1 ; off-sheet HP_SNS
HPL_OUT: C86.2 R73.1 ; off-sheet HPL_OUT
HPR_OUT: C89.2 R76.1 ; off-sheet HPR_OUT
MIC1_INN: D41.1(I/O2) J15.4(~{DET}) R68.1 R70.1 ; off-sheet MIC1_INN
MIC1_INP: C84.2 D42.1(I/O2) J16.2 R78.2 ; off-sheet MIC1_INP
PCA9539_IO1_0: Q1.1 ; off-sheet PCA9539_IO1_0  [also labelled SPK_CTL_H]
PCA9539_IO1_1: Q2.1 ; off-sheet PCA9539_IO1_1  [also labelled SPK_MUTE_H]
SARADC_VIN2_HP_HOOK: C81.2 R70.2 R71.1 ; off-sheet SARADC_VIN2_HP_HOOK
SPK_CTL_H_: Q1.3 U13.12(~{SD})
SPK_MUTE_H_: Q2.3 U13.5(~{MUTE})
VOLN: C87.1 D46.1(I/O2) J17.4 L17.2 TP27.1
VOLP: C88.1 D45.1(I/O2) J17.3 L18.2 TP26.1
VORN: C90.1 D44.1(I/O2) J17.2 L19.2 TP25.1
VORP: C91.1 D43.1(I/O2) J17.1 L20.2 TP24.1
NetC80_2: C80.2 R68.2 R69.1
NetC83_2: C83.2 R75.2 R78.1
NetC85_2: C85.2 U13.8(Bypass)
NetC86_1: C86.1 R79.1
NetC89_1: C89.1 R80.1
NetD38_1: D38.1(I/O2) J15.3(R) R76.2
NetD39_1: D39.1(I/O2) J15.5(L-COM) R74.2
NetD40_1: D40.1(I/O2) J15.2(L) R73.2
NetL17_1: L17.1 U13.3(VOLN)
NetL18_1: L18.1 U13.1(VOLP)
NetL19_1: L19.1 U13.14(VORN)
NetL20_1: L20.1 U13.16(VORP)
NetR79_2: R79.2 U13.7(INL)
NetR80_2: R80.2 U13.10(INR)

Not connected (* = marked no-connect by the designer): J15 6(R-COM)*

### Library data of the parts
C80 = C-0402_Dup1: Part Number: C020102120064; Part Name: 贴片电容; Manufacture: 三星¦国巨¦村田; PCB Footprint: C0402L; ERP Number: 1010200054; DSC1: ±10%; DSC3: X5R; ID: 64
C81 C82 C94 = C-0402_Dup1: as C37 on sheet P07
C83 = C-0402_Dup1: Manufacture: 三星¦国巨¦村田; Part Name: 贴片电容; Part Number: C020102120064; PCB Footprint: C0402L; ID: 64; DSC3: X5R; DSC1: ±10%; ERP Number: 1010200054
C84 = C-0402_Dup1: Part Number: C020102120045; Part Name: 贴片电容; Manufacture: 三星¦国巨¦村田; PCB Footprint: C0402L; ERP Number: 1010200149; DSC1: ±5%; DSC3: C0G; ID: 45
C85 = C-0402_Dup1: Manufacture: 三星¦国巨¦村田; Part Name: 贴片电容; Part Number: C020102120064; ID: 64; DSC3: X5R; DSC1: ±10%; ERP Number: 1010200054; PCB Footprint: C0402L
C86 C89 = C-0402_Dup1: as C74 on sheet P08
C87 C88 C90 C91 = C-0402_Dup1: Part Number: C020102120054; Part Name: 贴片电容; Manufacture: 三星¦国巨¦村田; ERP Number: 1010200084; DSC1: ±10%; DSC3: X7R; ID: 54; PCB Footprint: C0402L
C92 = C-0603: as C41 on sheet P07
C93 = C-0603: as C45 on sheet P07
C95 = C-0402_Dup1: as C36 on sheet P07
D38-D41 D45 = DI-ESD: as D14 on sheet P07
D42-D44 D46 = DI-ESD: as D13 on sheet P07
J15 = J-PJ-316A-6A: Part Name: 音频耳机座; Part Number: J050502940002; ID: 10; DSC4: PJ-316A-6A(韩荣); DSC2: 14*6*4mm; DSC1: 3.5mm贴片式耳机座 凸头 6P 单定位柱
J16 = J-H-2P: Part Number: J020302820001; Part Name: PH; DSC1: 2p; DSC2: 2.0mm间距; DSC3: 通孔180度直针; DSC4: 米黄色胶壳 耐高温; DSC5: A2001WV-2P(CJT); ID: 11
J17 = J-A-4P: Part Name: PH; Part Number: J020302820060; ID: 28; DSC5: A2001WR-S-4P(CJT); DSC4: 米黄色胶壳 耐高温; DSC3: 卧贴; DSC2: 2.0mm间距; DSC1: 4p
L16-L21 = FB-0603: as L11 on sheet P08
L22 = FB-0603: as L13 on sheet P08
Q1 Q2 = S-NPN_Dup1: Manufacture: 长电; Part Name: 数字三极管; Part Number: C030302200002; ID: 2; DSC4: 150mW; DSC3: Vce=50V; DSC2: Ic=100mA; DSC1: NPN; ERP Number: 1010800049
R68 R78 = R-0402_Dup1: Part Name: 贴片电阻; Part Number: C011002080778; DSC1: ±1%; DSC2: 1/16W; ID: 778
R69 = R-0402_Dup1: Part Number: C011002080630; Part Name: 贴片电阻; ID: 630; DSC2: 1/16W; DSC1: ±1%; ERP Number: 1010200450
R70 R71 = R-0402_Dup1: as R45 on sheet P08
R72 = R-0402_Dup1: Part Number: C011002080976; Part Name: 贴片电阻; ID: 976; DSC2: 1/16W; DSC1: ±1%; ERP Number: 1010200137
R73 R76 = R-0402_Dup1: as R31 on sheet P07
R74 = R-0402_Dup1: Part Number: C011002080742; Part Name: 贴片电阻; ID: 742; DSC2: 1/16W; DSC1: ±1%; ERP Number: 1010200113
R75 = R-0402_Dup1: as R62 on sheet P09
R77 = R-0402_Dup1: as R30 on sheet P07
R79 R80 = R-0402_Dup1: as R37 on sheet P07
TP24-TP27 = TP-TEST: Part Number: CAD; Part Name: 测试点; DSC1: 焊盘1mm; DSC2: 无孔; DSC3: 圆形; DSC4: 单面; ID: 3
U13 = U-NS4205: Manufacture: Nsiway(纳芯威); Part Number: C150102670002; Part Name: 功放; ID: 2; DSC3: -40~85℃; DSC1: 2*3W @4Ω,3~5.2V，Class D; ERP Number: 1010100190

## Sheet P11.SchDoc
size 297 x 209 mm
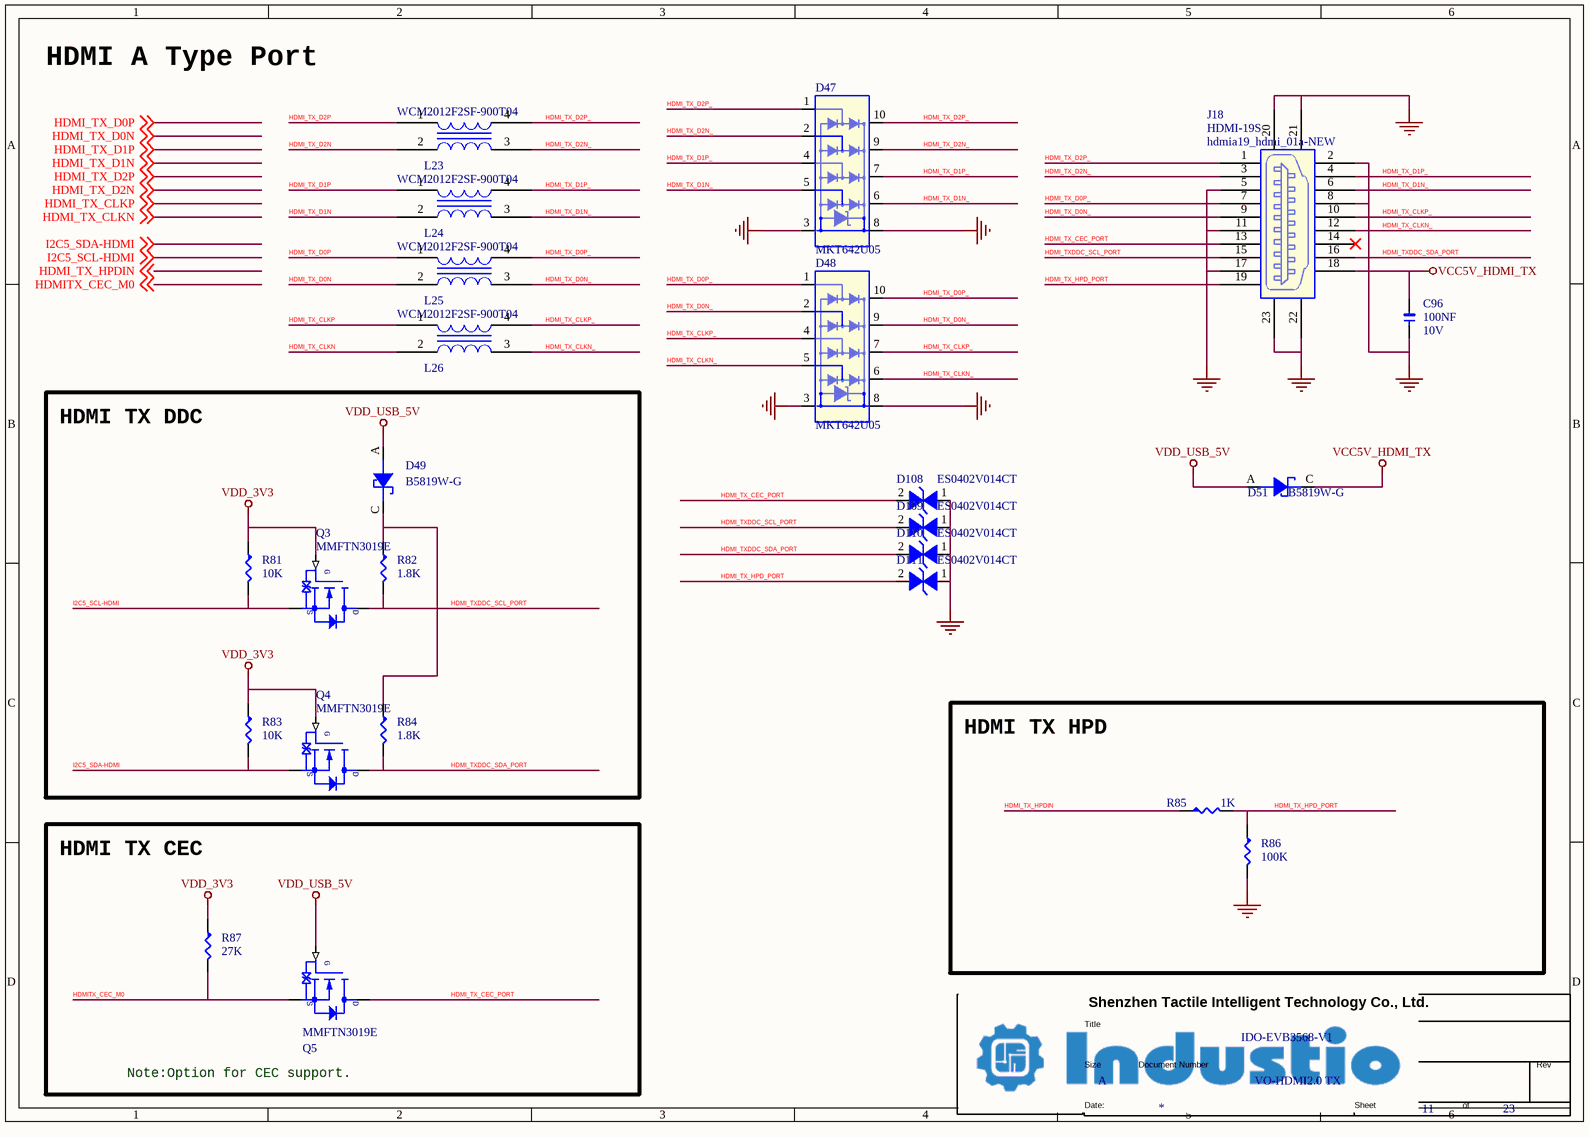
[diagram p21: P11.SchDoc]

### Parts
(Parts that share a designator on the sheet are numbered #1, #2 ... from top to bottom, then left to right.)
*#11  Doc: VO-HDMI2.0 TX  Title: IDO-EVB3568-V1  Page Size: A  Page Number: 11  Page Count: 23  (hidden comment: TitleBlock1)  (graphical)
C96  100NF  DSC2: 10V  [1206]
D47  MKT642U05  [ESD-DFN2510A-10]
D48  MKT642U05  [ESD-DFN2510A-10]
D49  B5819W-G  [SOD123]
D51  B5819W-G  [SOD123]
D108  ES0402V014CT  [V0402]
D109  ES0402V014CT  [V0402]
D110  ES0402V014CT  [V0402]
D111  ES0402V014CT  [V0402]
J18  HDMI-19S  [hdmia19_hdmi_01a-NEW]
L23  WCM2012F2SF-900T04  [CMLS-ACM2012]
L24  WCM2012F2SF-900T04  [CMLS-ACM2012]
L25  WCM2012F2SF-900T04  [CMLS-ACM2012]
L26  WCM2012F2SF-900T04  [CMLS-ACM2012]
Q3  MMFTN3019E  [SOT523]
Q4  MMFTN3019E  [SOT523]
Q5  MMFTN3019E  [SOT523]
R81  10K  [R0402L]
R82  1.8K  [R0402L]
R83  10K  [R0402L]
R84  1.8K  [R0402L]
R85  1K  [R0402L]
R86  100K  [R0402L]
R87  27K  [R0402L]

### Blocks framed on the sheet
HDMI TX DDC: D49 Q3 Q4 R81-R84
HDMI TX HPD: R85 R86
HDMI TX CEC: Q5 R87

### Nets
GND: C96.1 D47.3 D47.8 D48.3 D48.8 D108.1(I/O2) D109.1(I/O2) D110.1(I/O2) D111.1(I/O2) J18.2 J18.5 J18.8 J18.11 J18.17 J18.20 J18.21 J18.22 J18.23 R86.2
VCC5V_HDMI_TX: C96.2 D51.C J18.18
VDD_3V3: Q3.1(GATE) Q4.1(GATE) R81.1 R83.1 R87.1
VDD_USB_5V: D49.A D51.A Q5.1(GATE)
HDMI_TX_CEC_PORT: D108.2(I/O1) J18.13 Q5.3(DRAIN)
HDMI_TX_CLKN: L26.2 ; off-sheet HDMI_TX_CLKN
HDMI_TX_CLKN_: D48.5 D48.6 J18.12 L26.3
HDMI_TX_CLKP: L26.1 ; off-sheet HDMI_TX_CLKP
HDMI_TX_CLKP_: D48.4 D48.7 J18.10 L26.4
HDMI_TX_D0N: L25.2 ; off-sheet HDMI_TX_D0N
HDMI_TX_D0N_: D48.2 D48.9 J18.9 L25.3
HDMI_TX_D0P: L25.1 ; off-sheet HDMI_TX_D0P
HDMI_TX_D0P_: D48.1 D48.10 J18.7 L25.4
HDMI_TX_D1N: L24.2 ; off-sheet HDMI_TX_D1N
HDMI_TX_D1N_: D47.5 D47.6 J18.6 L24.3
HDMI_TX_D1P: L24.1 ; off-sheet HDMI_TX_D1P
HDMI_TX_D1P_: D47.4 D47.7 J18.4 L24.4
HDMI_TX_D2N: L23.2 ; off-sheet HDMI_TX_D2N
HDMI_TX_D2N_: D47.2 D47.9 J18.3 L23.3
HDMI_TX_D2P: L23.1 ; off-sheet HDMI_TX_D2P
HDMI_TX_D2P_: D47.1 D47.10 J18.1($PIN0) L23.4
HDMI_TX_HPD_PORT: D111.2(I/O1) J18.19 R85.2 R86.1
HDMI_TX_HPDIN: R85.1 ; off-sheet HDMI_TX_HPDIN
HDMI_TXDDC_SCL_PORT: D109.2(I/O1) J18.15 Q3.3(DRAIN) R82.2
HDMI_TXDDC_SDA_PORT: D110.2(I/O1) J18.16 Q4.3(DRAIN) R84.2
HDMITX_CEC_M0: Q5.2(SOURCE) R87.2 ; off-sheet HDMITX_CEC_M0
I2C5_SCL-HDMI: Q3.2(SOURCE) R81.2 ; off-sheet I2C5_SCL-HDMI  [project net HDMITX_SCL/I2C5_SCL_M1/GPIO4_C7_u]
I2C5_SDA-HDMI: Q4.2(SOURCE) R83.2 ; off-sheet I2C5_SDA-HDMI  [project net HDMITX_SDA/I2C5_SDA_M1/GPIO4_D0_u]
NetD49_C: D49.C R82.1 R84.1

Not connected (* = marked no-connect by the designer): J18 14*

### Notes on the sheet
- HDMI A Type Port
- Note:Option for CEC support.

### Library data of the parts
C96 = C-0402_Dup1: as C60 on sheet P08
D47 D48 = DI-ESD-MKT642U05: as D18 on sheet P08
D49 D51 = DI-XI-S: Part Number: C040202220005; Part Name: 肖特基二级管; Manufacture: 长电; CLASS: IC; DSC1: VR=40V; DSC2: IF=1A; DSC3: VF=600mV/1A; DSC4: IR=1mA; ID: 5
D108-D111 = DI-ESD: as D14 on sheet P07
J18 = J-HDMI-19P: Part Name: HDMI座; Part Number: J050302920001; ID: 7; DSC3: 贴片; DSC2: 15*11.8*6mm; DSC1: HDMI 19P母座SMT铜壳四脚 黑胶LCP 耐高温
L23-L26 = L-CMLS-ACM2012: as L6 on sheet P07
Q3 Q5 = N-MOS-Q: Part Number: C030202190004; Part Name: N-MOS; Manufacture: 先科; ERP Number: 1010800011; DSC1: Vds=30V; DSC2: Id=100mA; DSC3: Vgs(th)=1.5V; DSC4: Vgs=±20V; DSC5: pd=150mW; ID: 4
Q4 = N-MOS-Q: Manufacture: 先科; Part Name: N-MOS; Part Number: C030202190004; ID: 4; DSC5: pd=150mW; DSC4: Vgs=±20V; DSC3: Vgs(th)=1.5V; DSC2: Id=100mA; DSC1: Vds=30V; ERP Number: 1010800011
R81 R83 = R-0402_Dup1: as R28 on sheet P07
R82 R84 = R-0402_Dup1: Part Name: 贴片电阻; Part Number: C011002080769; DSC1: ±1%; DSC2: 1/16W; ID: 769
R85 = R-0402_Dup1: as R74 on sheet P10
R86 = R-0402_Dup1: as R45 on sheet P08
R87 = R-0402_Dup1: Part Number: C011002080904; Part Name: 贴片电阻; ID: 904; DSC2: 1/16W; DSC1: ±1%

## Sheet P12.SchDoc
size 297 x 209 mm
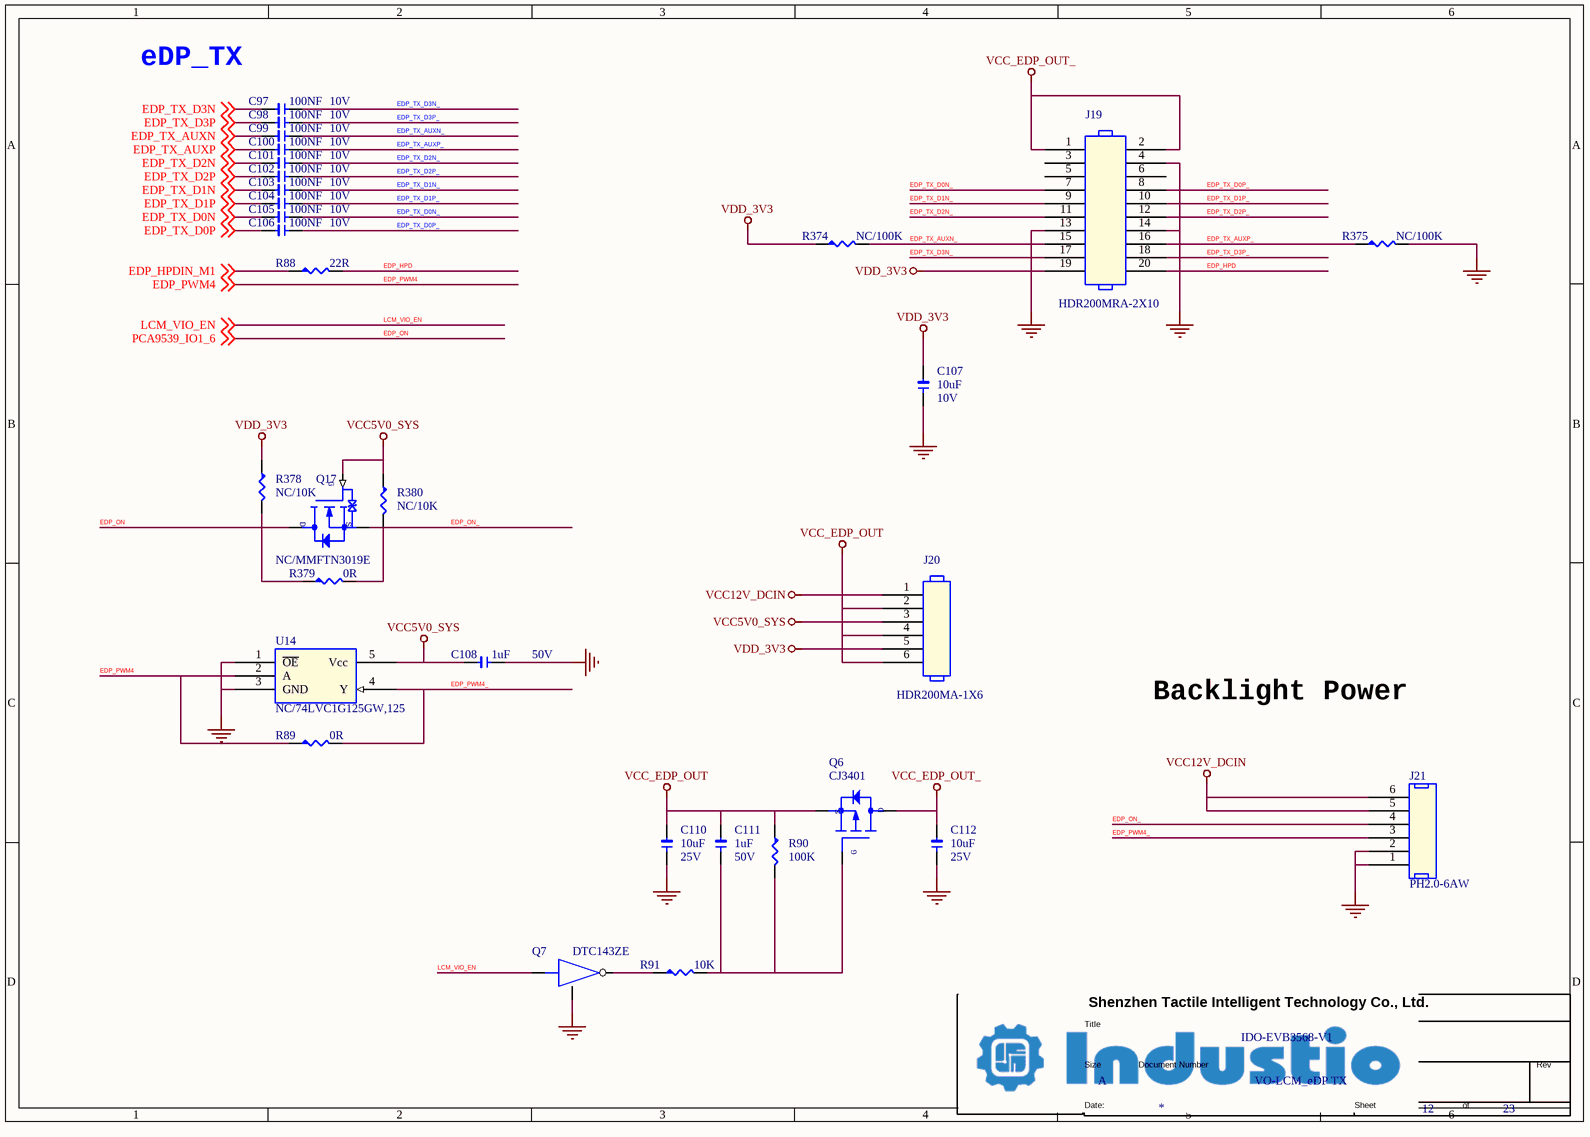
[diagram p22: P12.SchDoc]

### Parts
(Parts that share a designator on the sheet are numbered #1, #2 ... from top to bottom, then left to right.)
*#12  Doc: VO-LCM_eDP TX  Title: IDO-EVB3568-V1  Page Size: A  Page Number: 12  Page Count: 23  (hidden comment: TitleBlock1)  (graphical)
C97  100NF  DSC2: 10V  [1206]
C98  100NF  DSC2: 10V  [1206]
C99  100NF  DSC2: 10V  [1206]
C100  100NF  DSC2: 10V  [1206]
C101  100NF  DSC2: 10V  [1206]
C102  100NF  DSC2: 10V  [1206]
C103  100NF  DSC2: 10V  [1206]
C104  100NF  DSC2: 10V  [1206]
C105  100NF  DSC2: 10V  [1206]
C106  100NF  DSC2: 10V  [1206]
C107  10uF  DSC2: 10V  [1206]
C108  1uF  DSC2: 50V  [1206]
C110  10uF  DSC2: 25V  [1206]
C111  1uF  DSC2: 50V  [1206]
C112  10uF  DSC2: 25V  [1206]
J19  HDR200MRA-2X10  [HDR200MRA-2X10]
J20  HDR200MA-1X6  [HDR200MA-1X6]
J21  PH2.0-6AW  [PH200-6AW]
Q6  CJ3401  [SOT23]
Q7  DTC143ZE  [SOT523]
Q17  NC/MMFTN3019E  [SOT523]
R88  22R  [R0402L]
R89  0R  [R0402L]
R90  100K  [R0402L]
R91  10K  [R0402L]
R374  NC/100K  [R0402L]
R375  NC/100K  [R0402L]
R378  NC/10K  [R0402L]
R379  0R  [R0402L]
R380  NC/10K  [R0402L]
U14  NC/74LVC1G125GW,125  [SOT353]

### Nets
GND: C107.1 C108.1 C110.1 C112.1 J19.4 J19.13 J19.14 J21.1 J21.2 Q7.2 R375.2 U14.1(~{OE}) U14.3(GND)
VCC5V0_SYS: C108.2 J20.3 Q17.1(GATE) R380.1 U14.5(Vcc)
VCC12V_DCIN: J20.1 J21.5 J21.6
VCC_EDP_OUT: C110.2 C111.2 J20.2 J20.4 J20.6 Q6.2(SOURCE) R90.1
VCC_EDP_OUT_: C112.2 J19.1 J19.2 Q6.3(DRAIN)
VDD_3V3: C107.2 J19.19 J20.5 R374.1 R378.1
EDP_HPD: J19.20 R88.2
EDP_HPDIN_M1: R88.1 ; off-sheet EDP_HPDIN_M1  [project net PWM3_IR/EDP_HPDIN_M1/PCIE30X1_WAKEn_M0/MCU_JTAG_TMS/GPIO0_C2_d]
EDP_ON: Q17.3(DRAIN) R378.2 R379.1 ; off-sheet PCA9539_IO1_6  [also labelled PCA9539_IO1_6]
EDP_ON_: J21.4 Q17.2(SOURCE) R379.2 R380.2
EDP_PWM4: R89.1 U14.2(A) ; off-sheet EDP_PWM4
EDP_PWM4_: J21.3 R89.2 U14.4(Y)
EDP_TX_AUXN: C99.2 ; off-sheet EDP_TX_AUXN
EDP_TX_AUXN_: C99.1 J19.15 R374.2
EDP_TX_AUXP: C100.2 ; off-sheet EDP_TX_AUXP
EDP_TX_AUXP_: C100.1 J19.16 R375.1
EDP_TX_D0N: C105.2 ; off-sheet EDP_TX_D0N
EDP_TX_D0N_: C105.1 J19.7
EDP_TX_D0P: C106.2 ; off-sheet EDP_TX_D0P
EDP_TX_D0P_: C106.1 J19.8
EDP_TX_D1N: C103.2 ; off-sheet EDP_TX_D1N
EDP_TX_D1N_: C103.1 J19.9
EDP_TX_D1P: C104.2 ; off-sheet EDP_TX_D1P
EDP_TX_D1P_: C104.1 J19.10
EDP_TX_D2N: C101.2 ; off-sheet EDP_TX_D2N
EDP_TX_D2N_: C101.1 J19.11
EDP_TX_D2P: C102.2 ; off-sheet EDP_TX_D2P
EDP_TX_D2P_: C102.1 J19.12
EDP_TX_D3N: C97.2 ; off-sheet EDP_TX_D3N
EDP_TX_D3N_: C97.1 J19.17
EDP_TX_D3P: C98.2 ; off-sheet EDP_TX_D3P
EDP_TX_D3P_: C98.1 J19.18
LCM_VIO_EN: Q7.1 ; off-sheet LCM_VIO_EN
NetC111_1: C111.1 Q6.1(GATE) R90.2 R91.2
NetQ7_3: Q7.3 R91.1

Not connected (* = marked no-connect by the designer): J19 3 5 6

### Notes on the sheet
- eDP_TX
- Backlight Power

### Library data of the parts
C97 C98 = C-0402_Dup1: as C36 on sheet P07
C99-C106 = C-0402_Dup1: as C37 on sheet P07
C107 = C-0603: as C43 on sheet P07
C108 = C-0603: Part Number: C020102120069; Part Name: 贴片电容; Manufacture: 三星¦国巨¦村田; ERP Number: 1010200142; DSC1: ±10%; DSC3: X5R; ID: 69; PCB Footprint: C0603L
C110 = C-0805: Part Number: C020102120074; Part Name: 贴片电容; Manufacture: 三星¦国巨¦村田; ERP Number: 1010200144; DSC1: ±10%; DSC3: X5R; ID: 74; PCB Footprint: C0805L
C111 = C-0603: Manufacture: 三星¦国巨¦村田; Part Name: 贴片电容; Part Number: C020102120069; ID: 69; DSC3: X5R; DSC1: ±10%; ERP Number: 1010200142; PCB Footprint: C0603L
C112 = C-0805: Manufacture: 三星¦国巨¦村田; Part Name: 贴片电容; Part Number: C020102120074; ID: 74; DSC3: X5R; DSC1: ±10%; ERP Number: 1010200144; PCB Footprint: C0805L
J19 = J-HDR-D-20: Part Number: J010102760085; Part Name: 双排针; DSC1: 双排单塑; DSC2: 2x10; DSC3: 2mm脚距; DSC4: 通孔弯针; DSC5: 2.8+2(H塑高)+4 mm; DSC6: 黑胶; DSC7: A2005WR-2x10P（CJT); ID: 29
J20 = J-HDR-6: Part Number: J010206123880; Part Name: 单排针; DSC1: 单排单塑; DSC2: 1x6; DSC3: 2mm脚距; DSC4: 通孔直针; DSC5: 针长8.8mm  2.8+2(H塑高)+4 mm; DSC6: 黑胶; ID: 66
J21 = J-H-6P: Part Number: J020302820024; Part Name: PH; DSC1: 6p; DSC2: 2.0mm间距; DSC3: 通孔90度弯针; DSC4: 米黄色胶壳 耐高温; DSC5: A2001WR-6P(CJT); ID: 20
Q6 = P-MOS: Part Number: C030202190001; Manufacture: 长电; ERP Number: 1010800001; DSC1: Vds=-30V; DSC2: Id=-4.2A; DSC3: Vgs(th)=1.3V; DSC4: Vgs=±12V; DSC5: pd=350mW; ID: 1
Q7 = S-NPN_Dup1: Part Number: C030302200002; Part Name: 数字三极管; Manufacture: 长电; ERP Number: 1010800049; DSC1: NPN; DSC2: Ic=100mA; DSC3: Vce=50V; DSC4: 150mW; ID: 2
Q17 = N-MOS-Q: as Q3 on sheet P11
R88 = R-0402_Dup1: as R39 on sheet P08
R89 = R-0402_Dup1: as R31 on sheet P07
R90 R374 R375 = R-0402_Dup1: as R45 on sheet P08
R91 R378 R380 = R-0402_Dup1: as R46 on sheet P08
R379 = R-0402_Dup1: as R30 on sheet P07
U14 = U-74LVC1G125GW-125: Part Name: 逻辑缓冲器; Part Number: C080302460001; Manufacture: Nexperia(安世); ERP Number: 1010100128; DSC1: 1位 高速缓冲 三态输出 VCC=1.65V-5.5V; DSC2: SOT-353; DSC3: -55℃~+125℃; ID: 5

## Sheet P13.SchDoc
size 297 x 209 mm
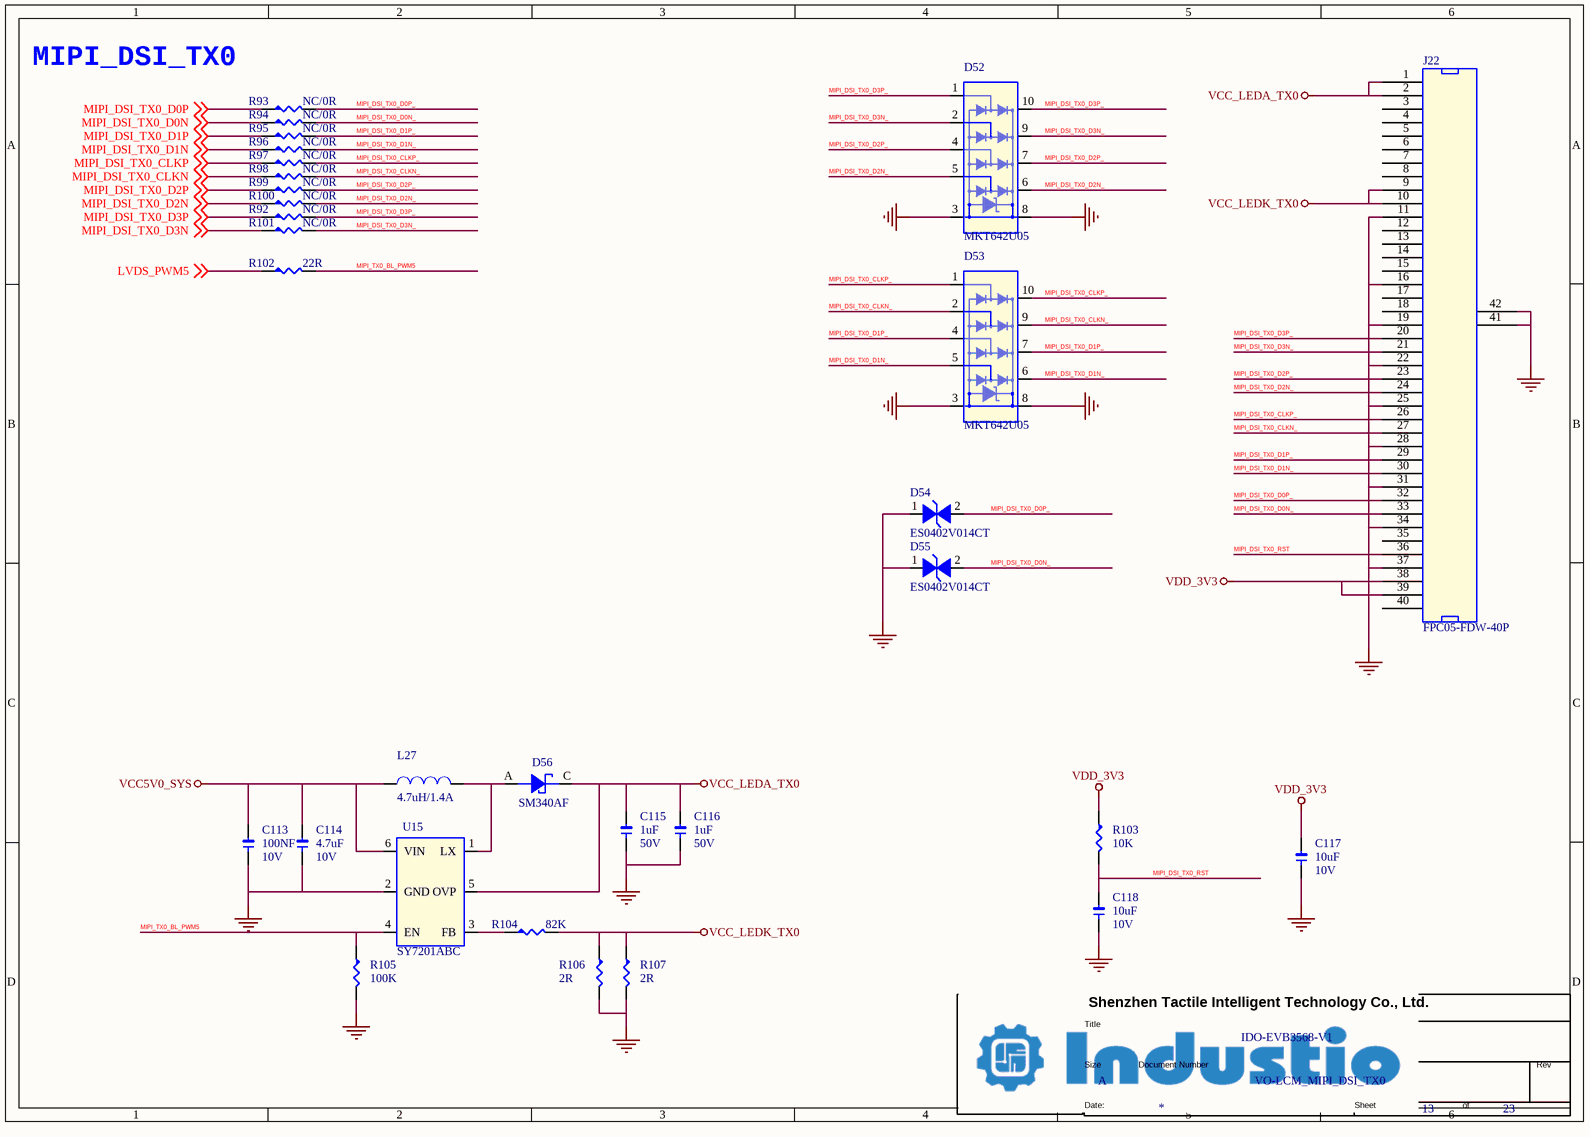
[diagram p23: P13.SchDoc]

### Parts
(Parts that share a designator on the sheet are numbered #1, #2 ... from top to bottom, then left to right.)
*#13  Doc: VO-LCM_MIPI_DSI_TX0  Title: IDO-EVB3568-V1  Page Size: A  Page Number: 13  Page Count: 23  (hidden comment: TitleBlock1)  (graphical)
C113  100NF  DSC2: 10V  [1206]
C114  4.7uF  DSC2: 10V  [1206]
C115  1uF  DSC2: 50V  [1206]
C116  1uF  DSC2: 50V  [1206]
C117  10uF  DSC2: 10V  [1206]
C118  10uF  DSC2: 10V  [1206]
D52  MKT642U05  [ESD-DFN2510A-10]
D53  MKT642U05  [ESD-DFN2510A-10]
D54  ES0402V014CT  [V0402]
D55  ES0402V014CT  [V0402]
D56  SM340AF  [SMAF]
J22  FPC05-FDW-40P  [FPC05-FDW-40P]
L27  4.7uH/1.4A  [L2520]
R92  NC/0R  [R0402L]
R93  NC/0R  [R0402L]
R94  NC/0R  [R0402L]
R95  NC/0R  [R0402L]
R96  NC/0R  [R0402L]
R97  NC/0R  [R0402L]
R98  NC/0R  [R0402L]
R99  NC/0R  [R0402L]
R100  NC/0R  [R0402L]
R101  NC/0R  [R0402L]
R102  22R  [R0402L]
R103  10K  [R0402L]
R104  82K  [R0402L]
R105  100K  [R0402L]
R106  2R  [R0805L]
R107  2R  [R0805L]
U15  SY7201ABC  [SOT23-6]

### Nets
GND: C113.1 C114.1 C115.1 C116.1 C117.1 C118.1 D52.3 D52.8 D53.3 D53.8 D54.1(I/O2) D55.1(I/O2) J22.11 J22.16 J22.19 J22.22 J22.25 J22.28 J22.31 J22.34 J22.37 J22.41 J22.42 R105.2 R106.2 R107.2 U15.2(GND)
VCC5V0_SYS: C113.2 C114.2 L27.1 U15.6(VIN)
VCC_LEDA_TX0: C115.2 C116.2 D56.C J22.1 J22.2 U15.5(OVP)
VCC_LEDK_TX0: J22.9 J22.10 R104.2 R106.1 R107.1
VDD_3V3: C117.2 J22.38 J22.39 R103.1
LVDS_PWM5: R102.1 ; off-sheet LVDS_PWM5
MIPI_DSI_TX0_CLKN: R98.1 ; off-sheet MIPI_DSI_TX0_CLKN
MIPI_DSI_TX0_CLKN_: D53.2 D53.9 J22.27 R98.2
MIPI_DSI_TX0_CLKP: R97.1 ; off-sheet MIPI_DSI_TX0_CLKP
MIPI_DSI_TX0_CLKP_: D53.1 D53.10 J22.26 R97.2
MIPI_DSI_TX0_D0N: R94.1 ; off-sheet MIPI_DSI_TX0_D0N
MIPI_DSI_TX0_D0N_: D55.2(I/O1) J22.33 R94.2
MIPI_DSI_TX0_D0P: R93.1 ; off-sheet MIPI_DSI_TX0_D0P
MIPI_DSI_TX0_D0P_: D54.2(I/O1) J22.32 R93.2
MIPI_DSI_TX0_D1N: R96.1 ; off-sheet MIPI_DSI_TX0_D1N
MIPI_DSI_TX0_D1N_: D53.5 D53.6 J22.30 R96.2
MIPI_DSI_TX0_D1P: R95.1 ; off-sheet MIPI_DSI_TX0_D1P
MIPI_DSI_TX0_D1P_: D53.4 D53.7 J22.29 R95.2
MIPI_DSI_TX0_D2N: R100.1 ; off-sheet MIPI_DSI_TX0_D2N
MIPI_DSI_TX0_D2N_: D52.5 D52.6 J22.24 R100.2
MIPI_DSI_TX0_D2P: R99.1 ; off-sheet MIPI_DSI_TX0_D2P
MIPI_DSI_TX0_D2P_: D52.4 D52.7 J22.23 R99.2
MIPI_DSI_TX0_D3N: R101.1 ; off-sheet MIPI_DSI_TX0_D3N
MIPI_DSI_TX0_D3N_: D52.2 D52.9 J22.21 R101.2
MIPI_DSI_TX0_D3P: R92.1 ; off-sheet MIPI_DSI_TX0_D3P
MIPI_DSI_TX0_D3P_: D52.1 D52.10 J22.20 R92.2
MIPI_DSI_TX0_RST: C118.2 J22.36 R103.2
MIPI_TX0_BL_PWM5: R102.2 R105.1 U15.4(EN)
NetD56_A: D56.A L27.2 U15.1(LX)
NetR104_1: R104.1 U15.3(FB)

Not connected (* = marked no-connect by the designer): J22 3 4 5 6 7 8 12 13 14 15 17 18 35 40

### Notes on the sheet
- MIPI_DSI_TX0

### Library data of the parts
C113 = C-0402_Dup1: as C74 on sheet P08
C114 = C-0402_Dup1: Manufacture: 三星¦国巨¦村田; Part Name: 贴片电容; Part Number: C020102120067; ID: 67; DSC3: X5R; DSC1: ±20%; PCB Footprint: C0402L
C115 = C-0603: as C111 on sheet P12
C116 = C-0603: as C108 on sheet P12
C117 C118 = C-0603: as C43 on sheet P07
D52 D53 = DI-ESD-MKT642U05: as D18 on sheet P08
D54 D55 = DI-ESD: as D13 on sheet P07
D56 = DI-XI-S: Part Number: C040202220007; Part Name: 肖特基二级管; Manufacture: 乐山无线电; CLASS: IC; DSC1: VR=40V; DSC2: IF=3A; DSC3: VF=500mV/3A; ID: 7; Solder: 推荐
J22 = J-FPC05-40P_Dup1: Part Name: FPC座; ID: 36; DSC6: X05A20L40T(星坤); DSC5: 镀锡; DSC4: H=2mm; DSC3: 下接 翻盖 卧贴; DSC2: 0.5mm间距; DSC1: 40P
L27 = L-IND: Part Name: 功率电感; Part Number: C060202340015; Manufacture: 顺络; DSC1: ±20%; DSC2: Isat=1.9A; DSC3: Irms=1.4A; DSC4: 240mΩ; DSC5: 2.5*2.0*1.0mm; DSC6: WPN252010U4R7MT(顺络)
R92-R101 = R-0402_Dup1: as R30 on sheet P07
R102 = R-0402_Dup1: Part Number: C011002080552; Part Name: 贴片电阻; ID: 552; DSC2: 1/16W; DSC1: ±1%
R103 = R-0402_Dup1: as R46 on sheet P08
R104 = R-0402_Dup1: Part Number: C011002080965; Part Name: 贴片电阻; ID: 965; DSC2: 1/16W; DSC1: ±1%
R105 = R-0402_Dup1: as R45 on sheet P08
R106 = R-0805: Part Name: 贴片电阻; Part Number: C011002081503; DSC1: ±1%; DSC2: 1/8W; ID: 1,503
R107 = R-0805: Part Number: C011002081503; Part Name: 贴片电阻; ID: 1,503; DSC2: 1/8W; DSC1: ±1%
U15 = U-SY7201A_2: Manufacture: 矽力杰; Part Number: C070202410024; Part Name: DCDC; ID: 24; Solder: 量产; DSC7: Boost LED驱动; DSC6: 1MHz; DSC5: 0.9; DSC4: Vfb=200mV; DSC3: Io=2A; DSC1: Vi=2.5-30V; ERP Number: 1010100053

## Sheet P14.SchDoc
size 297 x 209 mm
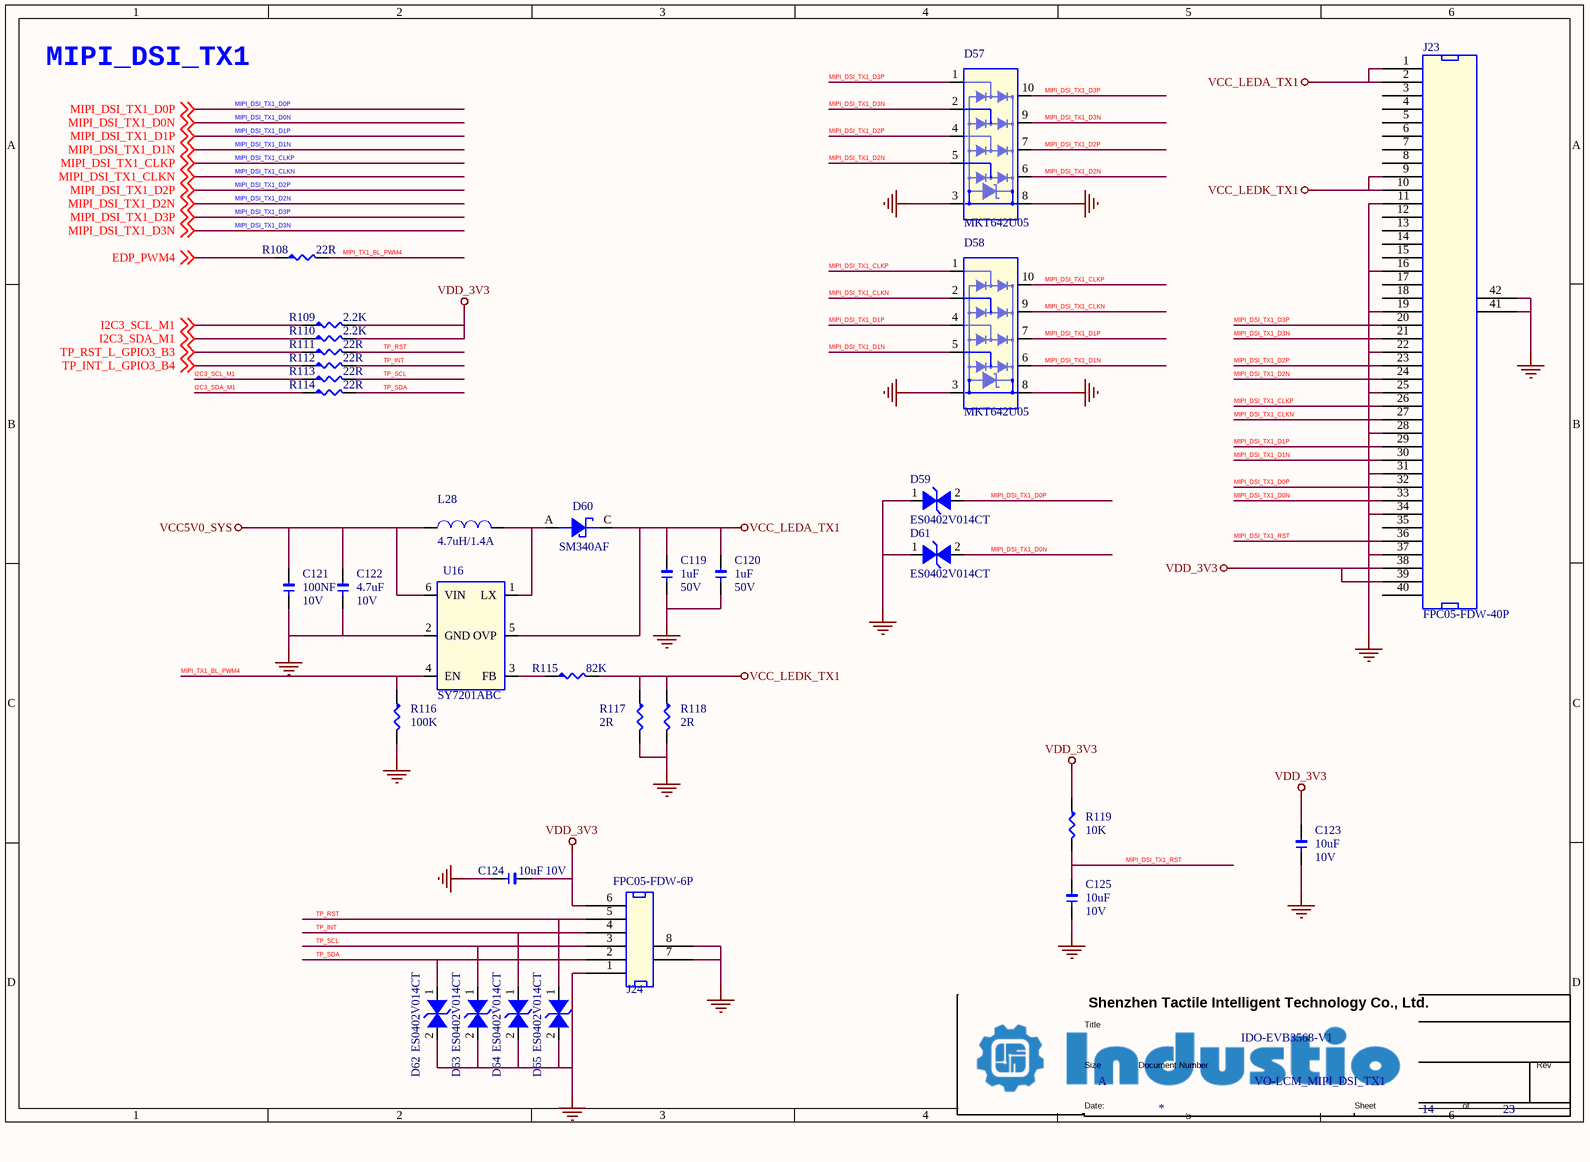
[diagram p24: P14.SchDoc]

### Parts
(Parts that share a designator on the sheet are numbered #1, #2 ... from top to bottom, then left to right.)
*#14  Doc: VO-LCM_MIPI_DSI_TX1  Title: IDO-EVB3568-V1  Page Size: A  Page Number: 14  Page Count: 23  (hidden comment: TitleBlock1)  (graphical)
C119  1uF  DSC2: 50V  [1206]
C120  1uF  DSC2: 50V  [1206]
C121  100NF  DSC2: 10V  [1206]
C122  4.7uF  DSC2: 10V  [1206]
C123  10uF  DSC2: 10V  [1206]
C124  10uF  DSC2: 10V  [1206]
C125  10uF  DSC2: 10V  [1206]
D57  MKT642U05  [ESD-DFN2510A-10]
D58  MKT642U05  [ESD-DFN2510A-10]
D59  ES0402V014CT  [V0402]
D60  SM340AF  [SMAF]
D61  ES0402V014CT  [V0402]
D62  ES0402V014CT  [V0402]
D63  ES0402V014CT  [V0402]
D64  ES0402V014CT  [V0402]
D65  ES0402V014CT  [V0402]
J23  FPC05-FDW-40P  [FPC05-FDW-40P]
J24  FPC05-FDW-6P  [FPC05-FDW-6P]
L28  4.7uH/1.4A  [L2520]
R108  22R  [R0402L]
R109  2.2K  [R0402L]
R110  2.2K  [R0402L]
R111  22R  [R0402L]
R112  22R  [R0402L]
R113  22R  [R0402L]
R114  22R  [R0402L]
R115  82K  [R0402L]
R116  100K  [R0402L]
R117  2R  [R0805L]
R118  2R  [R0805L]
R119  10K  [R0402L]
U16  SY7201ABC  [SOT23-6]

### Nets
GND: C119.1 C120.1 C121.1 C122.1 C123.1 C124.1 C125.1 D57.3 D57.8 D58.3 D58.8 D59.1(I/O2) D61.1(I/O2) D62.2(I/O1) D63.2(I/O1) D64.2(I/O1) D65.2(I/O1) J23.11 J23.16 J23.19 J23.22 J23.25 J23.28 J23.31 J23.34 J23.37 J23.41 J23.42 J24.1 J24.7 J24.8 R116.2 R117.2 R118.2 U16.2(GND)
VCC5V0_SYS: C121.2 C122.2 L28.1 U16.6(VIN)
VCC_LEDA_TX1: C119.2 C120.2 D60.C J23.1 J23.2 U16.5(OVP)
VCC_LEDK_TX1: J23.9 J23.10 R115.2 R117.1 R118.1
VDD_3V3: C123.2 C124.2 J23.38 J23.39 J24.6 R109.2 R110.2 R119.1
EDP_PWM4: R108.1 ; off-sheet EDP_PWM4
I2C3_SCL_M1: R109.1 R113.1 ; off-sheet I2C3_SCL_M1
I2C3_SDA_M1: R110.1 R114.1 ; off-sheet I2C3_SDA_M1
MIPI_DSI_TX1_CLKN: D58.2 D58.9 J23.27 ; off-sheet MIPI_DSI_TX1_CLKN
MIPI_DSI_TX1_CLKP: D58.1 D58.10 J23.26 ; off-sheet MIPI_DSI_TX1_CLKP
MIPI_DSI_TX1_D0N: D61.2(I/O1) J23.33 ; off-sheet MIPI_DSI_TX1_D0N
MIPI_DSI_TX1_D0P: D59.2(I/O1) J23.32 ; off-sheet MIPI_DSI_TX1_D0P
MIPI_DSI_TX1_D1N: D58.5 D58.6 J23.30 ; off-sheet MIPI_DSI_TX1_D1N
MIPI_DSI_TX1_D1P: D58.4 D58.7 J23.29 ; off-sheet MIPI_DSI_TX1_D1P
MIPI_DSI_TX1_D2N: D57.5 D57.6 J23.24 ; off-sheet MIPI_DSI_TX1_D2N
MIPI_DSI_TX1_D2P: D57.4 D57.7 J23.23 ; off-sheet MIPI_DSI_TX1_D2P
MIPI_DSI_TX1_D3N: D57.2 D57.9 J23.21 ; off-sheet MIPI_DSI_TX1_D3N
MIPI_DSI_TX1_D3P: D57.1 D57.10 J23.20 ; off-sheet MIPI_DSI_TX1_D3P
MIPI_DSI_TX1_RST: C125.2 J23.36 R119.2
MIPI_TX1_BL_PWM4: R108.2 R116.1 U16.4(EN)
TP_INT: D64.1(I/O2) J24.4 R112.2
TP_INT_L_GPIO3_B4: R112.1 ; off-sheet TP_INT_L_GPIO3_B4  [project net LCDC_D19/VOP_BT1120_D10/GMAC1_RXER_M0/I2C5_SDA_M0/PDM_SDI1_M2/GPIO3_B4_d]
TP_RST: D65.1(I/O2) J24.5 R111.2
TP_RST_L_GPIO3_B3: R111.1 ; off-sheet TP_RST_L_GPIO3_B3  [project net LCDC_D18/VOP_BT1120_D9/GMAC1_RXDV_CRS_M0/I2C5_SCL_M0/PDM_SDI0_M2/GPIO3_B3_d]
TP_SCL: D63.1(I/O2) J24.3 R113.2
TP_SDA: D62.1(I/O2) J24.2 R114.2
NetD60_A: D60.A L28.2 U16.1(LX)
NetR115_1: R115.1 U16.3(FB)

Not connected (* = marked no-connect by the designer): J23 3 4 5 6 7 8 12 13 14 15 17 18 35 40

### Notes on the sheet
- MIPI_DSI_TX1

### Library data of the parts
C119 = C-0603: Part Number: C020102120069; Part Name: 贴片电容; Manufacture: 三星¦国巨¦村田; PCB Footprint: C0603L; ERP Number: 1010200142; DSC1: ±10%; DSC3: X5R; ID: 69
C120 = C-0603: Manufacture: 三星¦国巨¦村田; Part Name: 贴片电容; Part Number: C020102120069; PCB Footprint: C0603L; ID: 69; DSC3: X5R; DSC1: ±10%; ERP Number: 1010200142
C121 = C-0402_Dup1: as C37 on sheet P07
C122 = C-0402_Dup1: Part Number: C020102120067; Part Name: 贴片电容; Manufacture: 三星¦国巨¦村田; PCB Footprint: C0402L; DSC1: ±20%; DSC3: X5R; ID: 67
C123-C125 = C-0603: as C45 on sheet P07
D57 D58 = DI-ESD-MKT642U05: as D18 on sheet P08
D59 D61 D63-D65 = DI-ESD: as D13 on sheet P07
D60 = DI-XI-S: Manufacture: 乐山无线电; Part Name: 肖特基二级管; Part Number: C040202220007; CLASS: IC; Solder: 推荐; ID: 7; DSC3: VF=500mV/3A; DSC2: IF=3A; DSC1: VR=40V
D62 = DI-ESD: as D14 on sheet P07
J23 = J-FPC05-40P_Dup1: as J22 on sheet P13
J24 = J-FPC05-6P: Part Name: FPC座; Part Number: J030102870054; ID: 13; DSC6: X05A20L06T(星坤); DSC5: 镀锡; DSC4: H=2mm; DSC3: 下接 翻盖 卧贴; DSC2: 0.5mm间距; DSC1: 6P
L28 = L-IND: Manufacture: 顺络; Part Number: C060202340015; Part Name: 功率电感; DSC6: WPN252010U4R7MT(顺络); DSC5: 2.5*2.0*1.0mm; DSC4: 240mΩ; DSC3: Irms=1.4A; DSC2: Isat=1.9A; DSC1: ±20%
R108 R111 R112 R114 = R-0402_Dup1: as R102 on sheet P13
R109 R110 = R-0402_Dup1: Part Number: C011002080778; Part Name: 贴片电阻; ID: 778; DSC2: 1/16W; DSC1: ±1%
R113 = R-0402_Dup1: as R39 on sheet P08
R115 = R-0402_Dup1: Part Name: 贴片电阻; Part Number: C011002080965; DSC1: ±1%; DSC2: 1/16W; ID: 965
R116 = R-0402_Dup1: as R72 on sheet P10
R117 = R-0805: as R107 on sheet P13
R118 = R-0805: as R106 on sheet P13
R119 = R-0402_Dup1: as R46 on sheet P08
U16 = U-SY7201A_2: Part Name: DCDC; Part Number: C070202410024; Manufacture: 矽力杰; ERP Number: 1010100053; DSC1: Vi=2.5-30V; DSC3: Io=2A; DSC4: Vfb=200mV; DSC5: 0.9; DSC6: 1MHz; DSC7: Boost LED驱动; Solder: 量产; ID: 24

## Sheet P15.SchDoc
size 420 x 297 mm
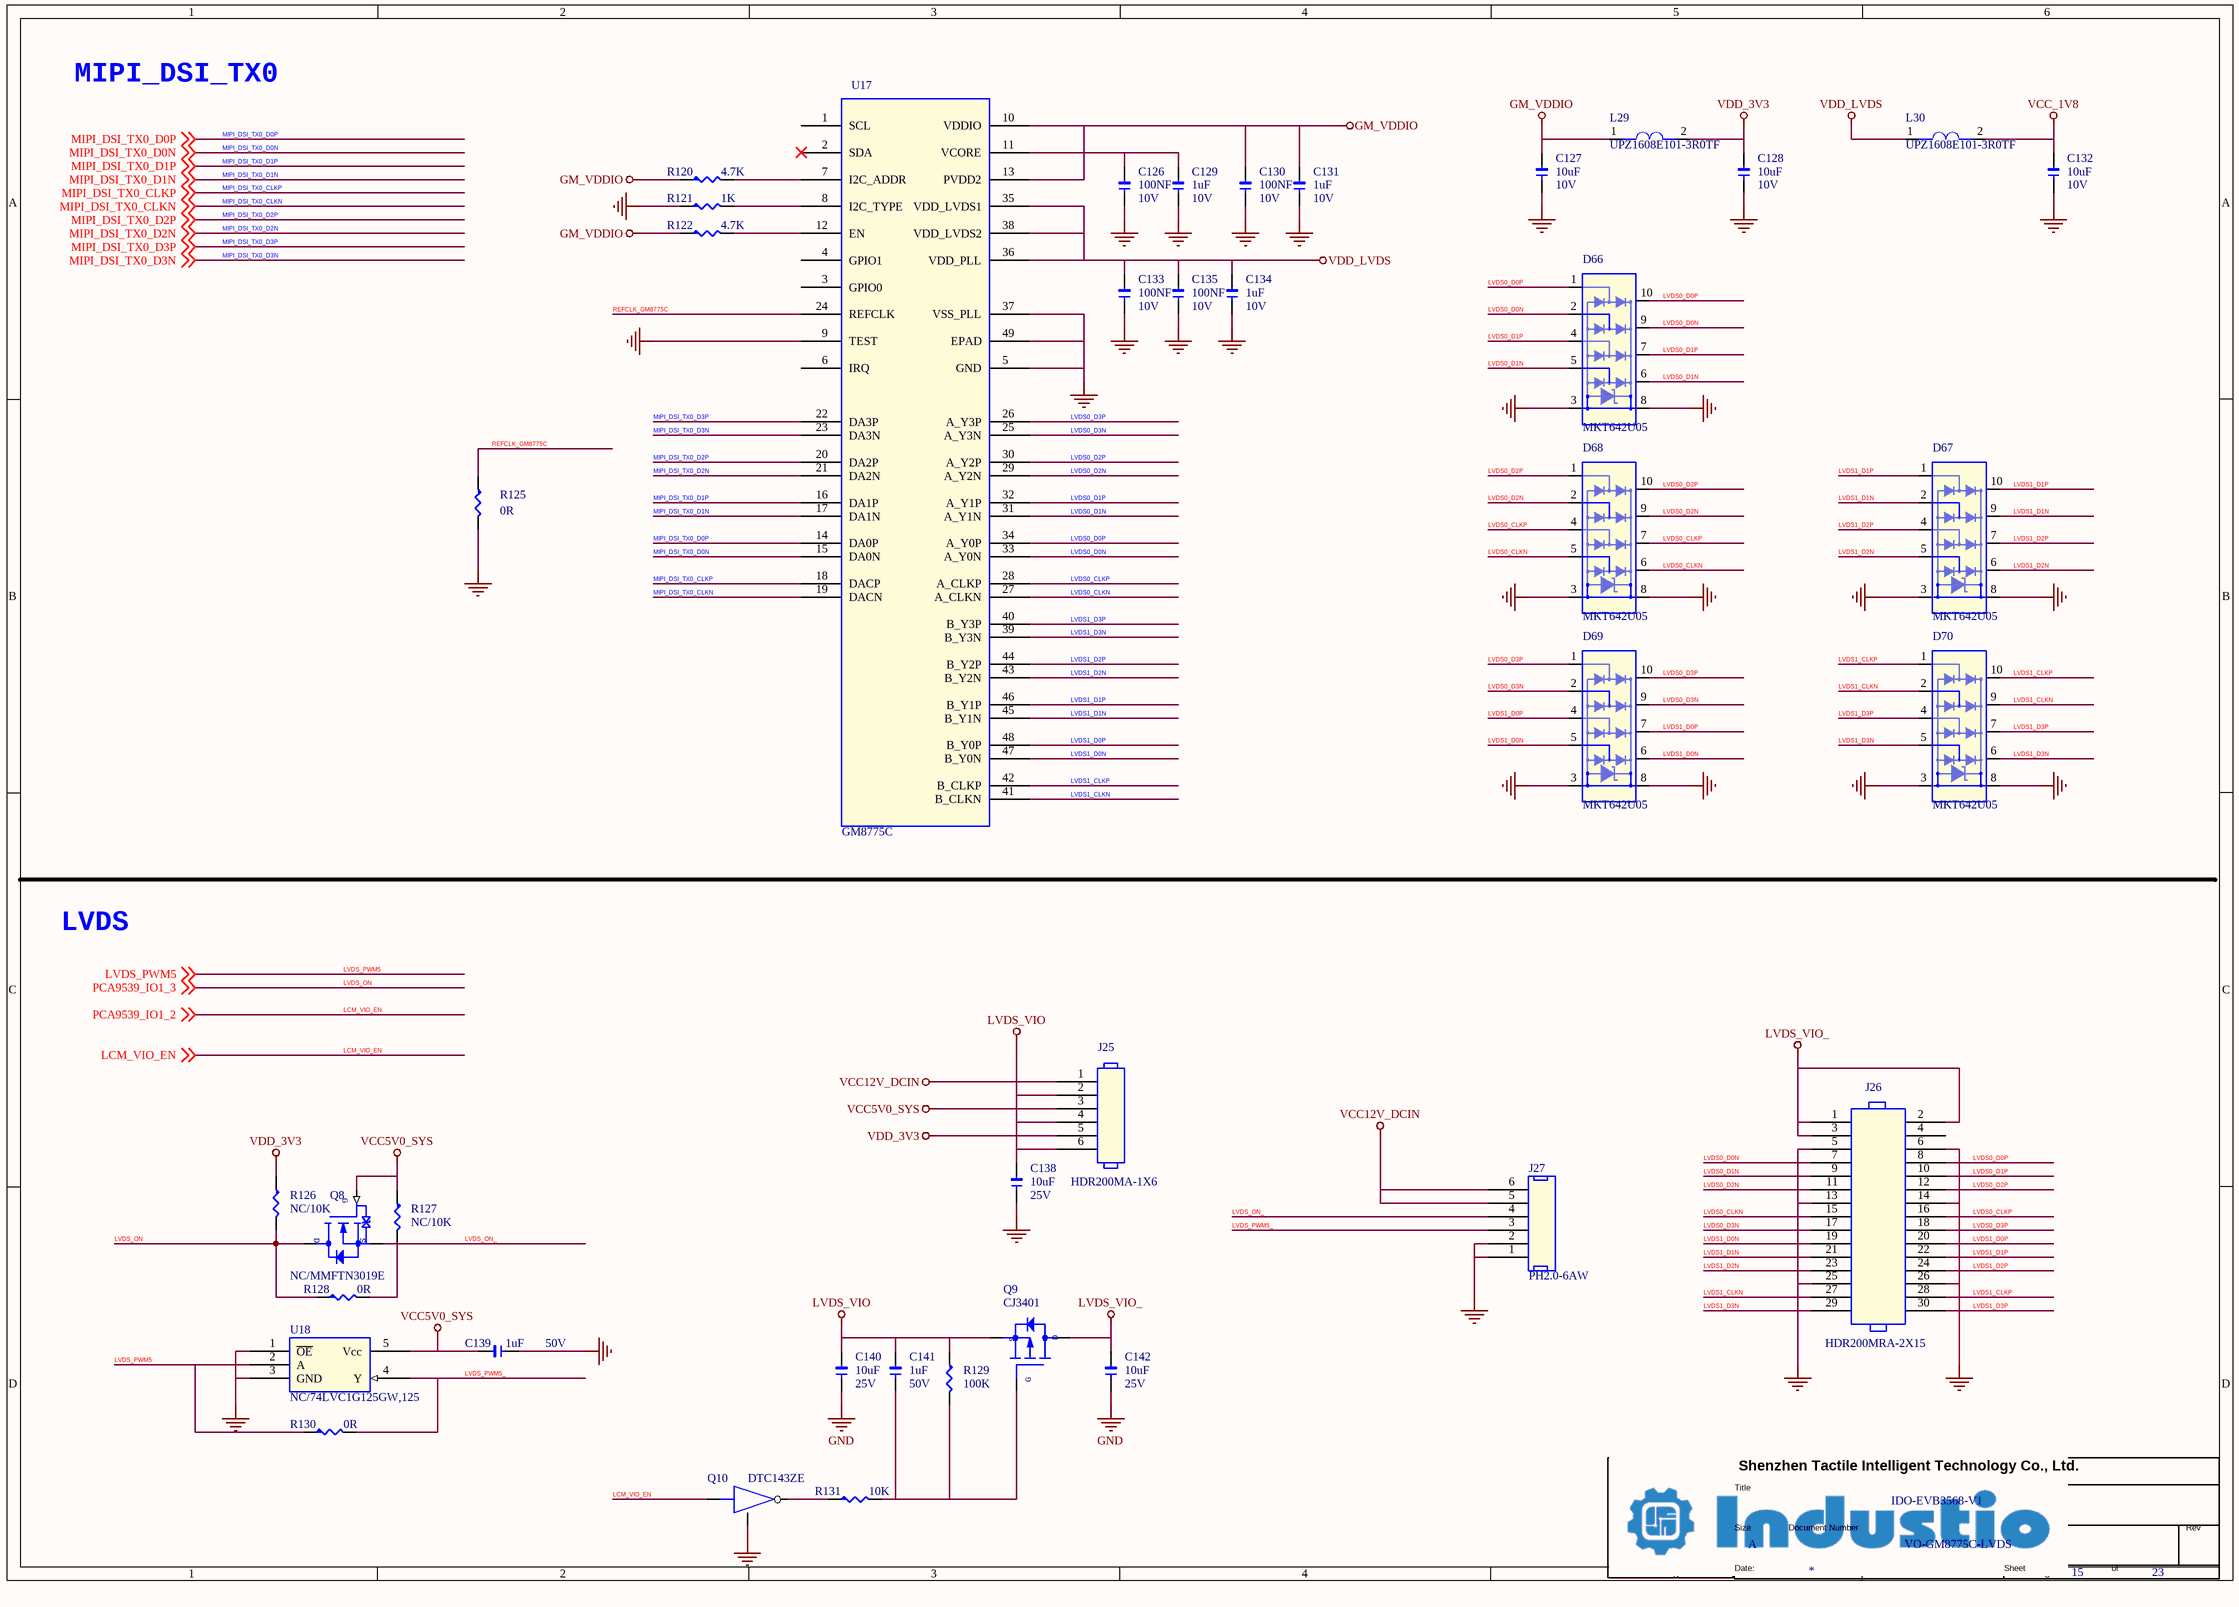
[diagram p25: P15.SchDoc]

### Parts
(Parts that share a designator on the sheet are numbered #1, #2 ... from top to bottom, then left to right.)
*#15  Doc: VO-GM8775C-LVDS  Title: IDO-EVB3568-V1  Page Size: A  Page Number: 15  Page Count: 23  (hidden comment: TitleBlock1)  (graphical)
C126  100NF  DSC2: 10V  [1206]
C127  10uF  DSC2: 10V  [1206]
C128  10uF  DSC2: 10V  [1206]
C129  1uF  DSC2: 10V  [1206]
C130  100NF  DSC2: 10V  [1206]
C131  1uF  DSC2: 10V  [1206]
C132  10uF  DSC2: 10V  [1206]
C133  100NF  DSC2: 10V  [1206]
C134  1uF  DSC2: 10V  [1206]
C135  100NF  DSC2: 10V  [1206]
C138  10uF  DSC2: 25V  [1206]
C139  1uF  DSC2: 50V  [1206]
C140  10uF  DSC2: 25V  [1206]
C141  1uF  DSC2: 50V  [1206]
C142  10uF  DSC2: 25V  [1206]
D66  MKT642U05  [ESD-DFN2510A-10]
D67  MKT642U05  [ESD-DFN2510A-10]
D68  MKT642U05  [ESD-DFN2510A-10]
D69  MKT642U05  [ESD-DFN2510A-10]
D70  MKT642U05  [ESD-DFN2510A-10]
J25  HDR200MA-1X6  [HDR200MA-1X6]
J26  HDR200MRA-2X15  [HDR200MRA-2X15]
J27  PH2.0-6AW  [PH200-6AW]
L29  UPZ1608E101-3R0TF  [L0603]
L30  UPZ1608E101-3R0TF  [L0603]
Q8  NC/MMFTN3019E  [SOT523]
Q9  CJ3401  [SOT23]
Q10  DTC143ZE  [SOT523]
R120  4.7K  [R0402L]
R121  1K  [R0402L]
R122  4.7K  [R0402L]
R125  0R  [R0402L]
R126  NC/10K  [R0402L]
R127  NC/10K  [R0402L]
R128  0R  [R0402L]
R129  100K  [R0402L]
R130  0R  [R0402L]
R131  10K  [R0402L]
U17  GM8775C  [qfn50p700x700x100-49an]
U18  NC/74LVC1G125GW,125  [SOT353]

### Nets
GM_VDDIO: C127.2 C130.2 C131.2 L29.1 R120.1 R122.1 U17.10(VDDIO) U17.13(PVDD2)
GND: C126.1 C127.1 C128.1 C129.1 C130.1 C131.1 C132.1 C133.1 C134.1 C135.1 C138.1 C139.1 C140.1 C142.1 D66.3 D66.8 D67.3 D67.8 D68.3 D68.8 D69.3 D69.8 D70.3 D70.8 J26.5 J26.6 J26.13 J26.14 J26.25 J26.26 J27.1 J27.2 Q10.2 R121.1 R125.2 U17.5(GND) U17.9(TEST) U17.37(VSS_PLL) U17.49(EPAD) U18.1(~{OE}) U18.3(GND)
LVDS_VIO: C138.2 C140.2 C141.2 J25.2 J25.4 J25.6 Q9.2(SOURCE) R129.1
LVDS_VIO_: C142.2 J26.1 J26.2 J26.3 Q9.3(DRAIN)
VCC5V0_SYS: C139.2 J25.3 Q8.1(GATE) R127.1 U18.5(Vcc)
VCC12V_DCIN: J25.1 J27.5 J27.6
VCC_1V8: C132.2 L30.2
VDD_3V3: C128.2 J25.5 L29.2 R126.1
VDD_LVDS: C133.2 C134.2 C135.2 L30.1 U17.35(VDD_LVDS1) U17.36(VDD_PLL) U17.38(VDD_LVDS2)
LCM_VIO_EN: Q10.1 ; off-sheet PCA9539_IO1_2, off-sheet LCM_VIO_EN  [also labelled PCA9539_IO1_2]
LVDS0_CLKN: D68.5 D68.6 J26.15 U17.27(A_CLKN)
LVDS0_CLKP: D68.4 D68.7 J26.16 U17.28(A_CLKP)
LVDS0_D0N: D66.2 D66.9 J26.7 U17.33(A_Y0N)
LVDS0_D0P: D66.1 D66.10 J26.8 U17.34(A_Y0P)
LVDS0_D1N: D66.5 D66.6 J26.9 U17.31(A_Y1N)
LVDS0_D1P: D66.4 D66.7 J26.10 U17.32(A_Y1P)
LVDS0_D2N: D68.2 D68.9 J26.11 U17.29(A_Y2N)
LVDS0_D2P: D68.1 D68.10 J26.12 U17.30(A_Y2P)
LVDS0_D3N: D69.2 D69.9 J26.17 U17.25(A_Y3N)
LVDS0_D3P: D69.1 D69.10 J26.18 U17.26(A_Y3P)
LVDS1_CLKN: D70.2 D70.9 J26.27 U17.41(B_CLKN)
LVDS1_CLKP: D70.1 D70.10 J26.28 U17.42(B_CLKP)
LVDS1_D0N: D69.5 D69.6 J26.19 U17.47(B_Y0N)
LVDS1_D0P: D69.4 D69.7 J26.20 U17.48(B_Y0P)
LVDS1_D1N: D67.2 D67.9 J26.21 U17.45(B_Y1N)
LVDS1_D1P: D67.1 D67.10 J26.22 U17.46(B_Y1P)
LVDS1_D2N: D67.5 D67.6 J26.23 U17.43(B_Y2N)
LVDS1_D2P: D67.4 D67.7 J26.24 U17.44(B_Y2P)
LVDS1_D3N: D70.5 D70.6 J26.29 U17.39(B_Y3N)
LVDS1_D3P: D70.4 D70.7 J26.30 U17.40(B_Y3P)
LVDS_ON: Q8.3(DRAIN) R126.2 R128.1 ; off-sheet PCA9539_IO1_3  [also labelled PCA9539_IO1_3]
LVDS_ON_: J27.4 Q8.2(SOURCE) R127.2 R128.2
LVDS_PWM5: R130.1 U18.2(A) ; off-sheet LVDS_PWM5
LVDS_PWM5_: J27.3 R130.2 U18.4(Y)
MIPI_DSI_TX0_CLKN: U17.19(DACN) ; off-sheet MIPI_DSI_TX0_CLKN
MIPI_DSI_TX0_CLKP: U17.18(DACP) ; off-sheet MIPI_DSI_TX0_CLKP
MIPI_DSI_TX0_D0N: U17.15(DA0N) ; off-sheet MIPI_DSI_TX0_D0N
MIPI_DSI_TX0_D0P: U17.14(DA0P) ; off-sheet MIPI_DSI_TX0_D0P
MIPI_DSI_TX0_D1N: U17.17(DA1N) ; off-sheet MIPI_DSI_TX0_D1N
MIPI_DSI_TX0_D1P: U17.16(DA1P) ; off-sheet MIPI_DSI_TX0_D1P
MIPI_DSI_TX0_D2N: U17.21(DA2N) ; off-sheet MIPI_DSI_TX0_D2N
MIPI_DSI_TX0_D2P: U17.20(DA2P) ; off-sheet MIPI_DSI_TX0_D2P
MIPI_DSI_TX0_D3N: U17.23(DA3N) ; off-sheet MIPI_DSI_TX0_D3N
MIPI_DSI_TX0_D3P: U17.22(DA3P) ; off-sheet MIPI_DSI_TX0_D3P
REFCLK_GM8775C: R125.1 U17.24(REFCLK)
NetC126_2: C126.2 C129.2 U17.11(VCORE)
NetC141_1: C141.1 Q9.1(GATE) R129.2 R131.2
NetQ10_3: Q10.3 R131.1
NetR120_2: R120.2 U17.7(I2C_ADDR)
NetR121_2: R121.2 U17.8(I2C_TYPE)
NetR122_2: R122.2 U17.12(EN)

Not connected (* = marked no-connect by the designer): J26 4(17); U17 1(SCL) 2(SDA)* 3(GPIO0) 4(GPIO1) 6(IRQ)

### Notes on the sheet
- MIPI_DSI_TX0
- LVDS

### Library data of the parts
C126 C130 = C-0402_Dup1: as C74 on sheet P08
C127 C128 C132 = C-0603: as C41 on sheet P07
C129 C131 = C-0402_Dup1: Part Number: C020102120064; Part Name: 贴片电容; Manufacture: 三星¦国巨¦村田; ERP Number: 1010200054; DSC1: ±10%; DSC3: X5R; ID: 64; PCB Footprint: C0402L
C133 C135 = C-0402_Dup1: as C60 on sheet P08
C134 = C-0402_Dup1: as C85 on sheet P10
C138 C140 = C-0805: Part Number: C020102120074; Part Name: 贴片电容; Manufacture: 三星¦国巨¦村田; PCB Footprint: C0805L; ERP Number: 1010200144; DSC1: ±10%; DSC3: X5R; ID: 74
C139 = C-0603: as C111 on sheet P12
C141 = C-0603: as C120 on sheet P14
C142 = C-0805: Manufacture: 三星¦国巨¦村田; Part Name: 贴片电容; Part Number: C020102120074; PCB Footprint: C0805L; ID: 74; DSC3: X5R; DSC1: ±10%; ERP Number: 1010200144
D66 D68 D69 = DI-ESD-MKT642U05: as D15 on sheet P07
D67 D70 = DI-ESD-MKT642U05: as D18 on sheet P08
J25 = J-HDR-6: Part Name: 单排针; Part Number: J010206123880; ID: 66; DSC6: 黑胶; DSC5: 针长8.8mm  2.8+2(H塑高)+4 mm; DSC4: 通孔直针; DSC3: 2mm脚距; DSC2: 1x6; DSC1: 单排单塑
J26 = J-HDR-D-30: Part Name: 双排针; Part Number: J010102760090; ID: 30; DSC7: A2005WR-2x15P（CJT); DSC6: 黑胶; DSC5: 2.8+2(H塑高)+4 mm; DSC4: 通孔弯针; DSC3: 2mm脚距; DSC2: 2x15; DSC1: 双排单塑
J27 = J-H-6P: Part Name: PH; Part Number: J020302820024; ID: 20; DSC5: A2001WR-6P(CJT); DSC4: 米黄色胶壳 耐高温; DSC3: 通孔90度弯针; DSC2: 2.0mm间距; DSC1: 6p
L29 = FB-0603: as L11 on sheet P08
L30 = FB-0603: as L13 on sheet P08
Q8 = N-MOS-Q: as Q3 on sheet P11
Q9 = P-MOS: as Q6 on sheet P12
Q10 = S-NPN_Dup1: as Q7 on sheet P12
R120 R122 = R-0402_Dup1: as R35 on sheet P07
R121 = R-0402_Dup1: Part Name: 贴片电阻; Part Number: C011002080742; ERP Number: 1010200113; DSC1: ±1%; DSC2: 1/16W; ID: 742
R125 = R-0402_Dup1: as R31 on sheet P07
R126 R127 R131 = R-0402_Dup1: as R46 on sheet P08
R128 R130 = R-0402_Dup1: as R30 on sheet P07
R129 = R-0402_Dup1: as R45 on sheet P08
U18 = U-74LVC1G125GW-125: Manufacture: Nexperia(安世); Part Number: C080302460001; Part Name: 逻辑缓冲器; ID: 5; DSC3: -55℃~+125℃; DSC2: SOT-353; DSC1: 1位 高速缓冲 三态输出 VCC=1.65V-5.5V; ERP Number: 1010100128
